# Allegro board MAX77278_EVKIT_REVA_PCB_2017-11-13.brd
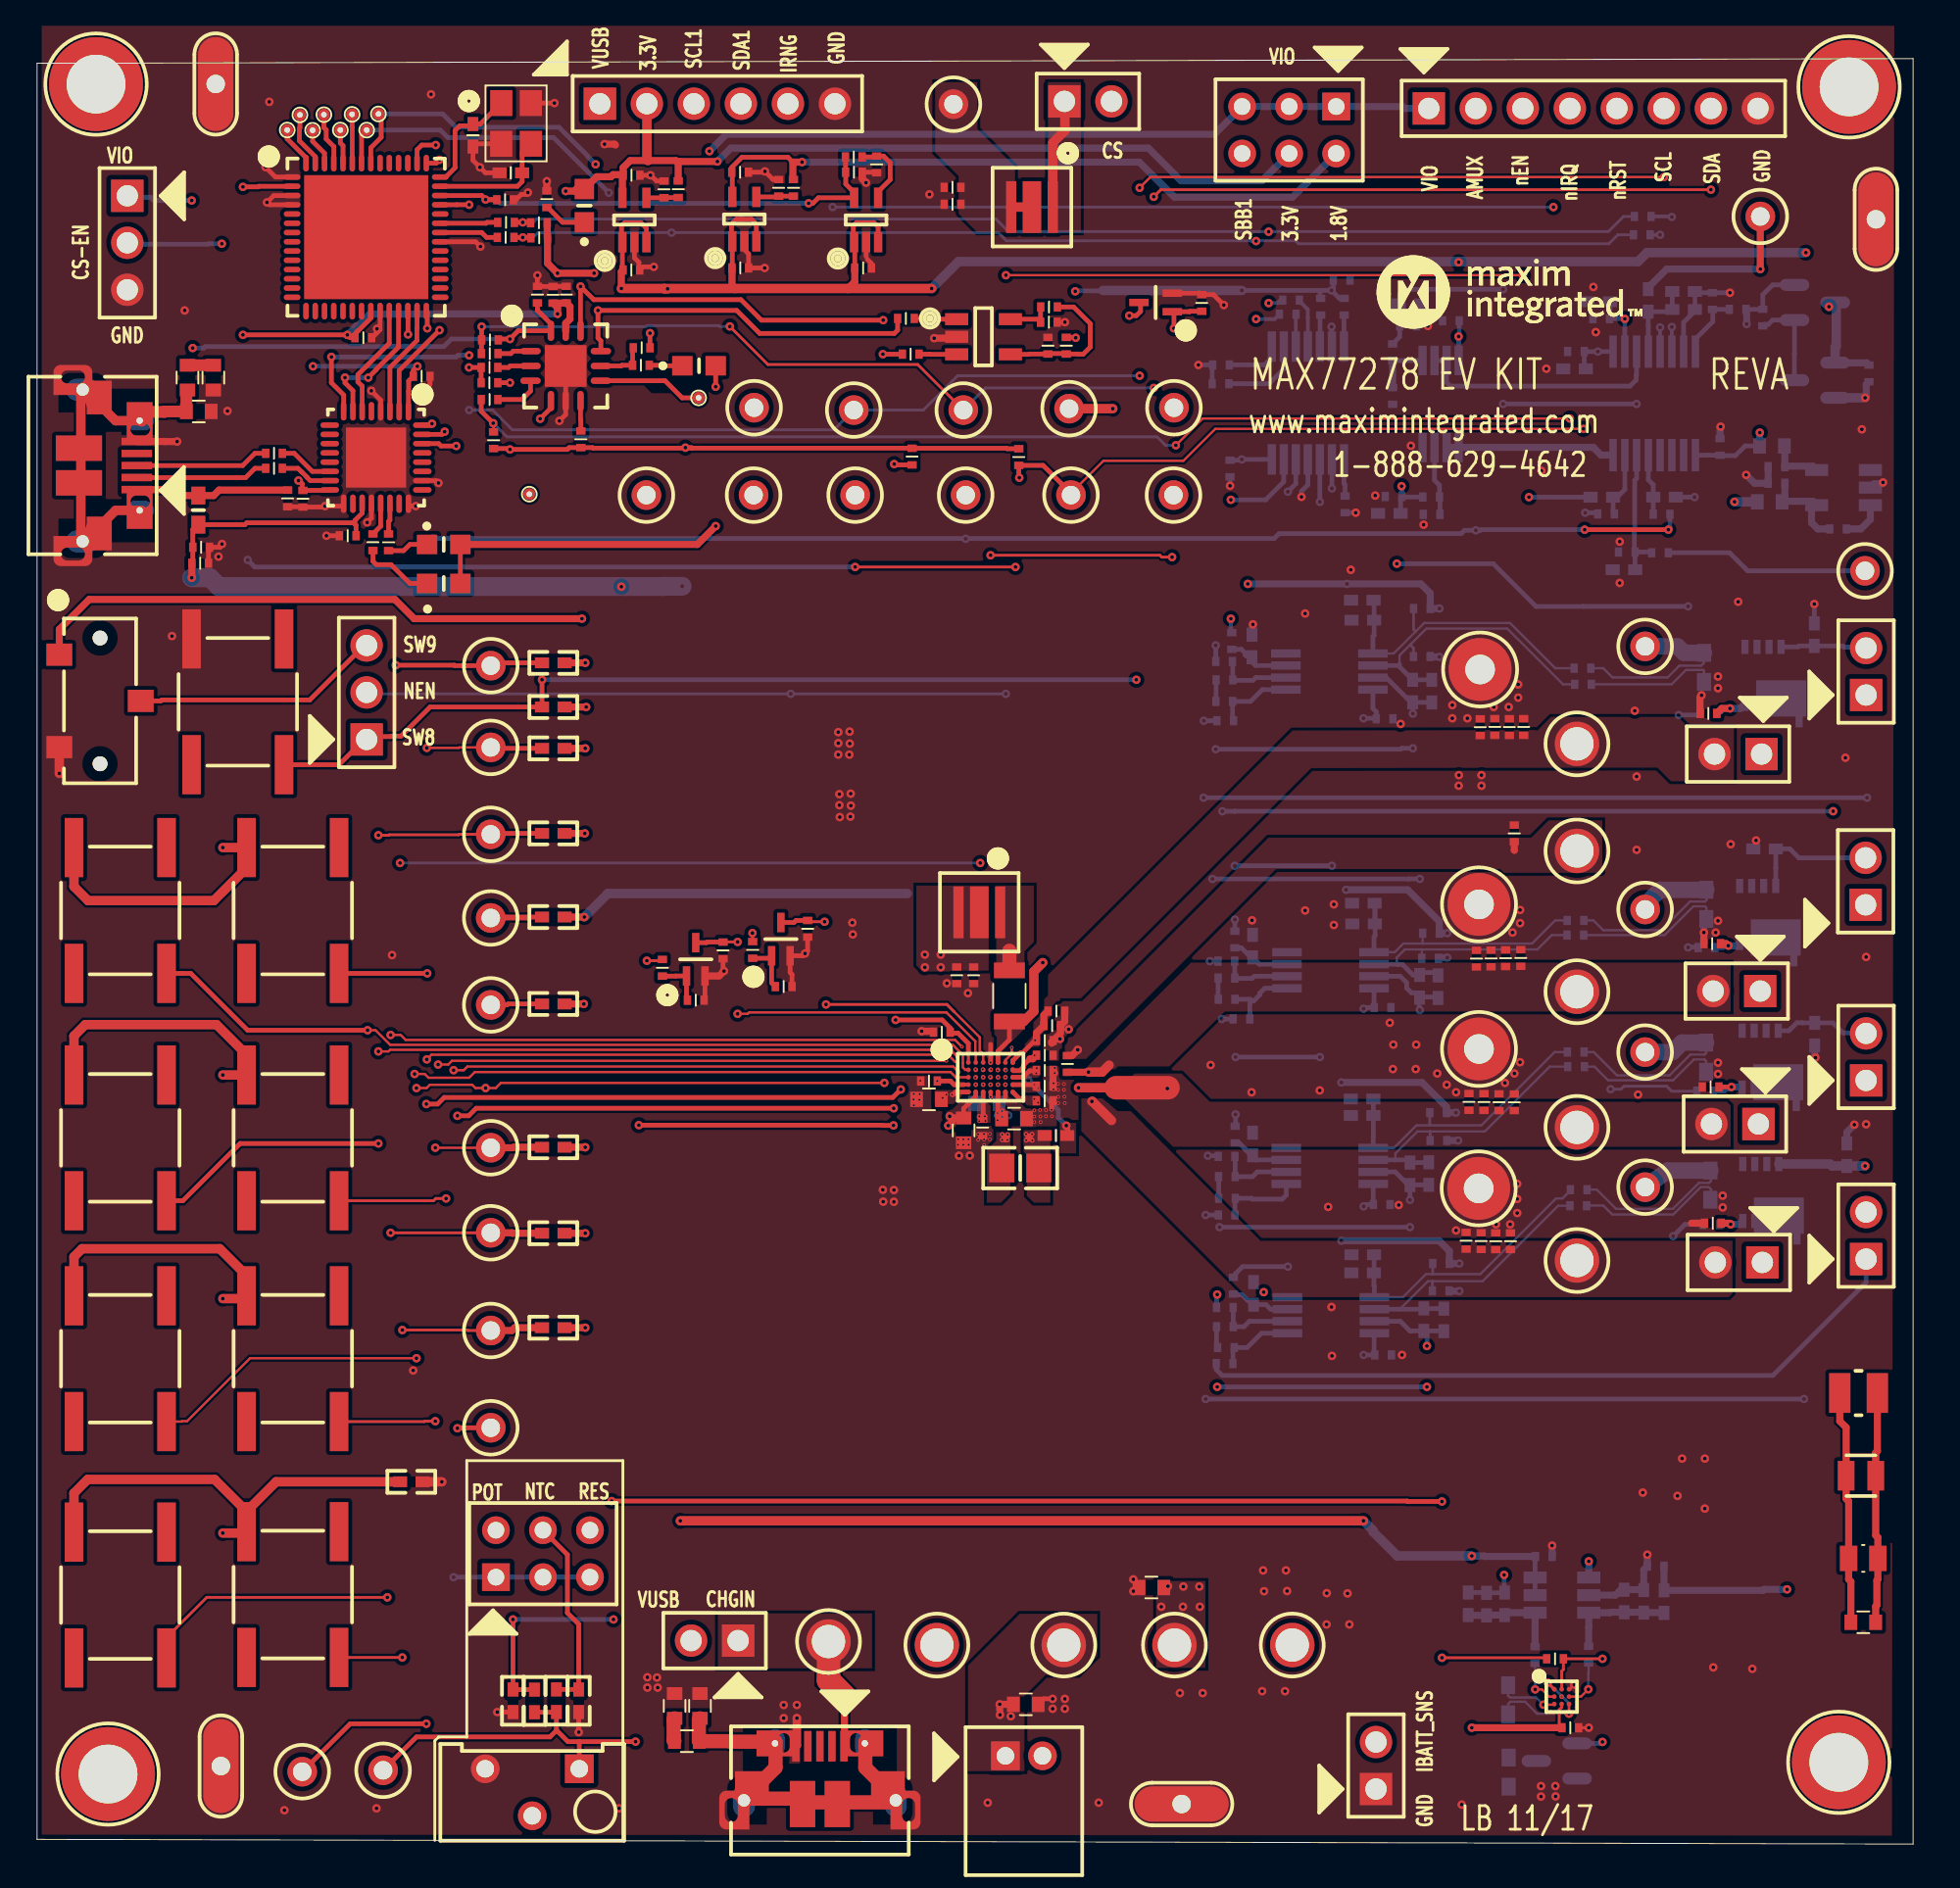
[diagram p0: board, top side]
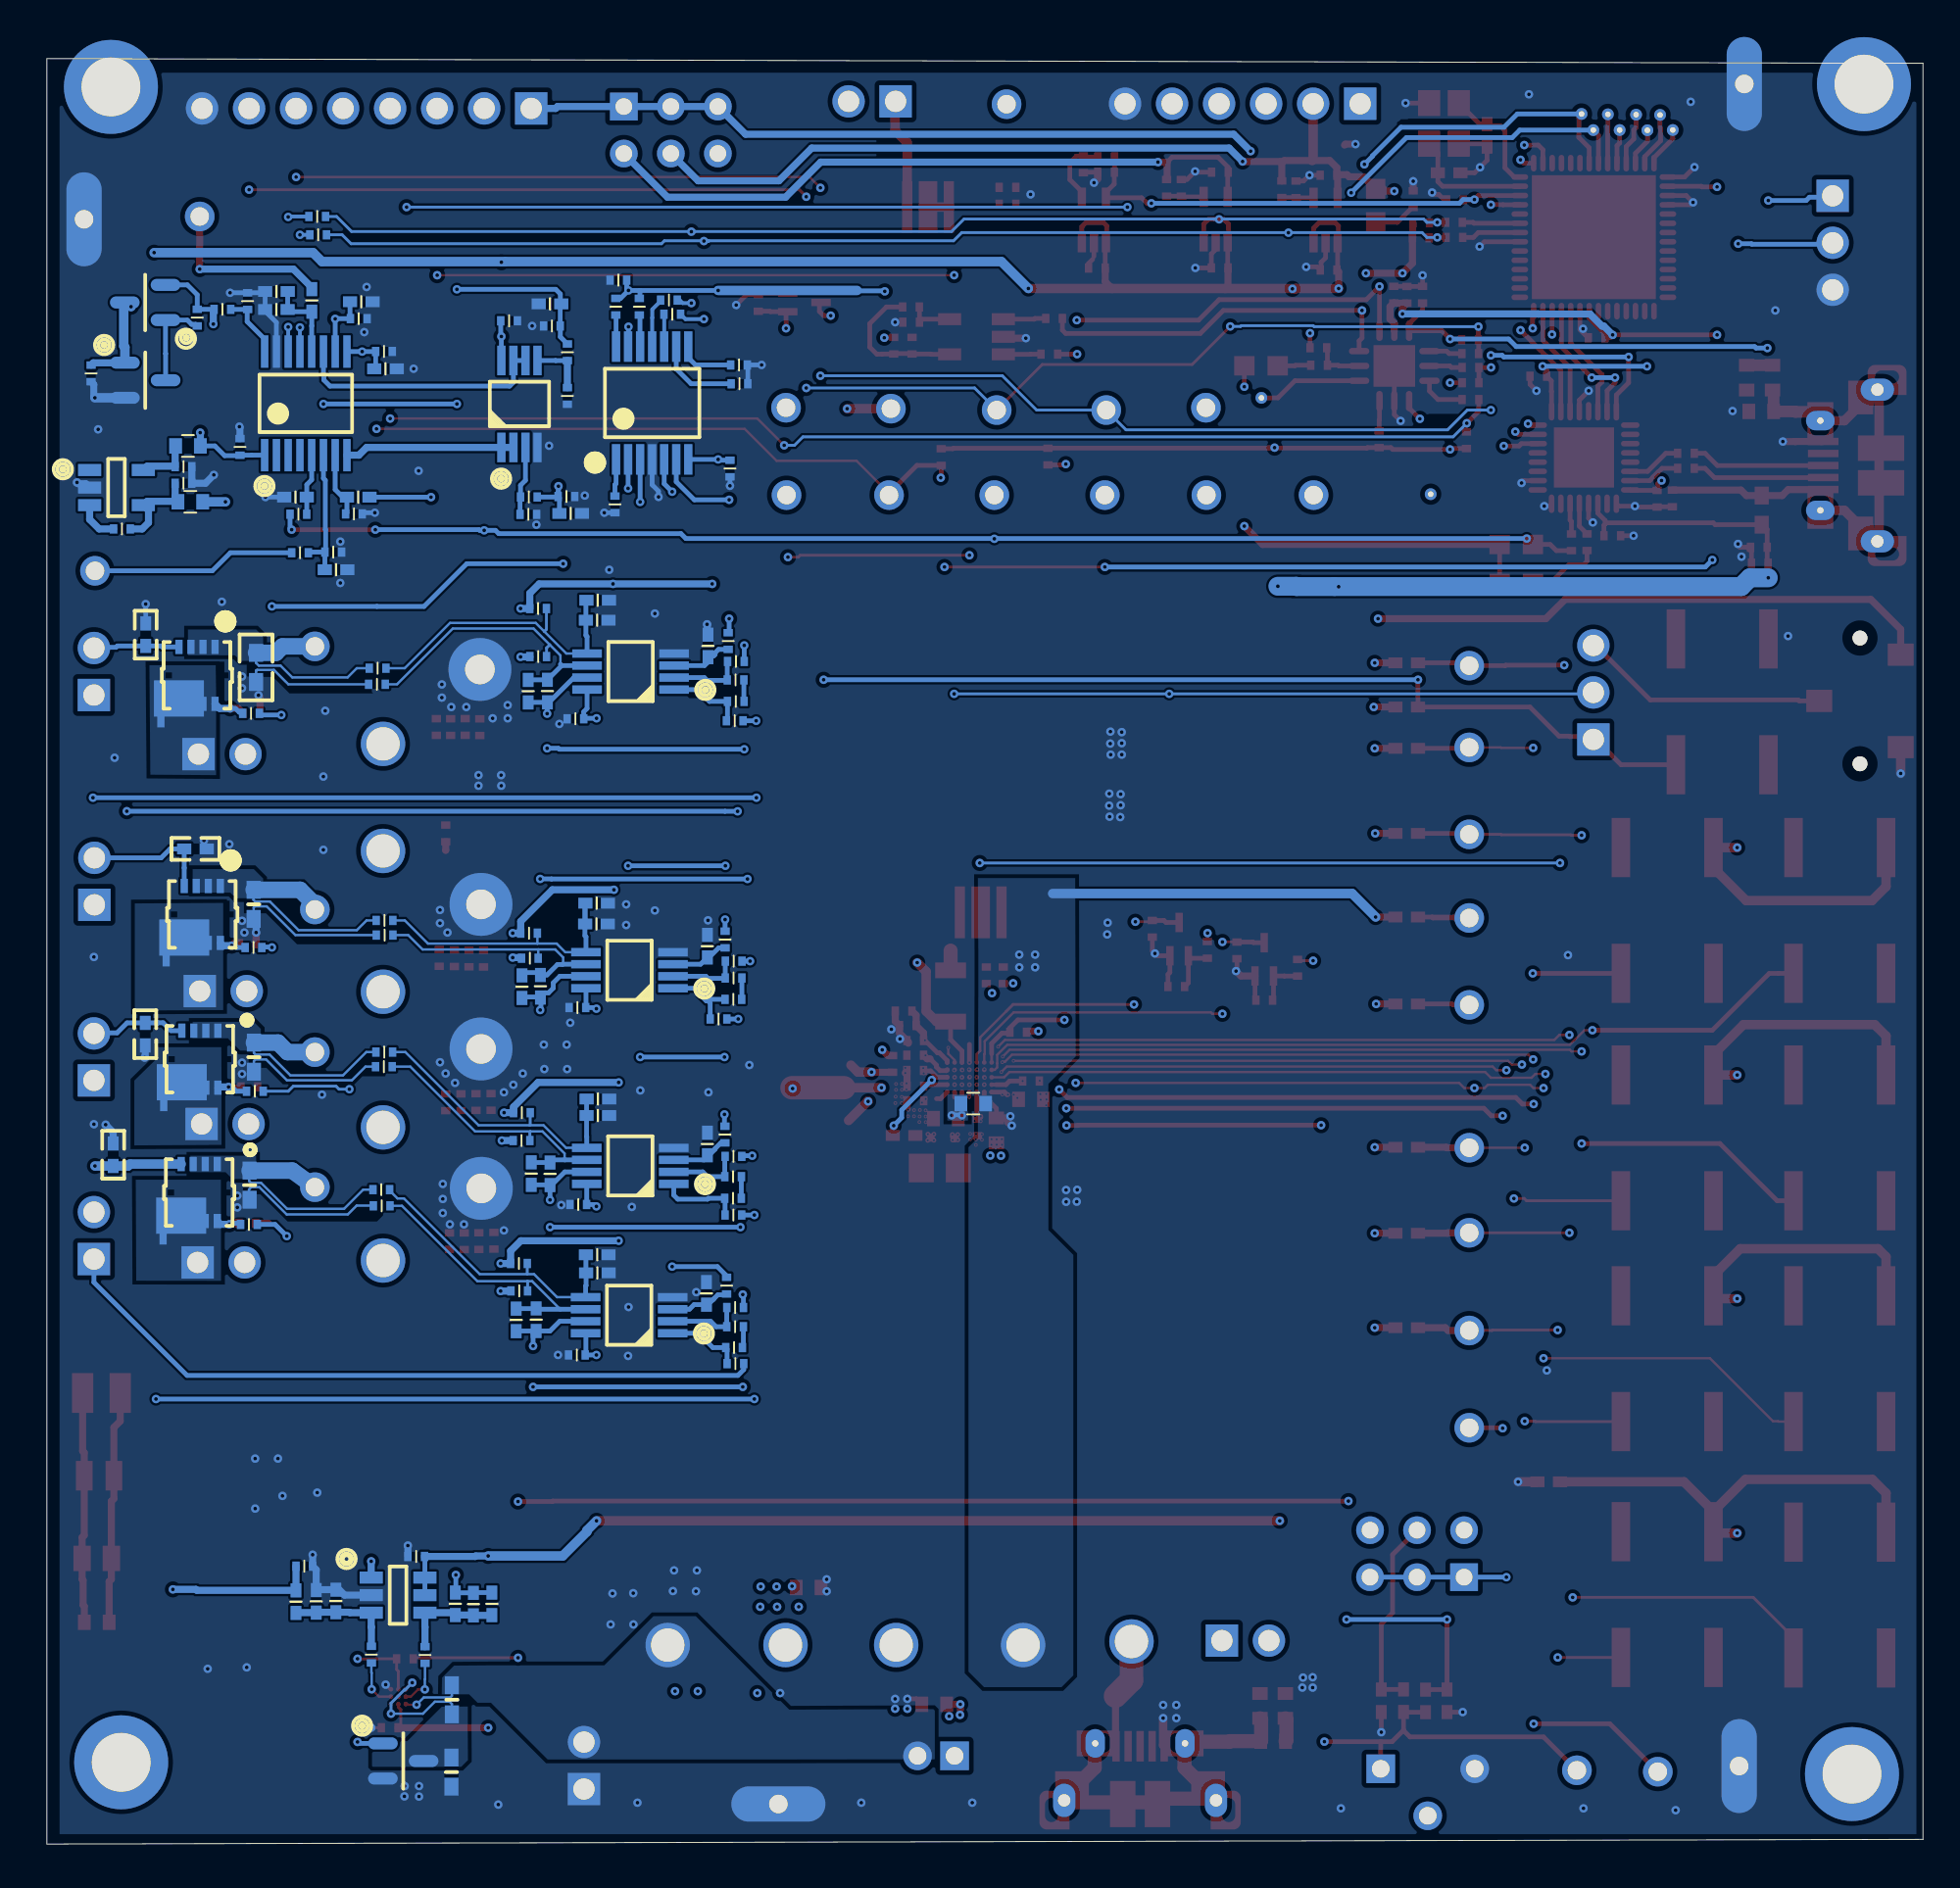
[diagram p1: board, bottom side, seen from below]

Outline 101.35 x 96.52 mm; copper layers: TOP, INTERNAL2, INTERNAL3, BOTTOM. Coordinates in mm from the lower left corner of the outline.
Outline path: 0,96.27 0,0.25 101.35,0 101.35,96.52 0,96.27

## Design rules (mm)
constraint set DEFAULT: min track width 0.102
net group NIRQ: nets NIRQ UNNAMED_4_EKRESSMD_I87_1
net group NIRQ1: nets NIRQ1 UNNAMED_4_EKRESSMD_I190_2
net group UNNAMED_1_10103592-0001LF_I172_SHIELD10: nets UNNAMED_1_10103592-0001LF_I172_SHIELD10 UNNAMED_1_EKCAPNP_I55_1
net group UNNAMED_4_10103592-0001LF_I212_2: nets UNNAMED_4_10103592-0001LF_I212_2 UNNAMED_4_EKRESSMD_I15_2
net group UNNAMED_4_10103592-0001LF_I212_3: nets UNNAMED_4_10103592-0001LF_I212_3 UNNAMED_4_EKRESSMD_I16_2
net group UNNAMED_4_10103592-0001LF_I212_SHIELD10: nets UNNAMED_4_10103592-0001LF_I212_SHIELD10 UNNAMED_4_EKCAPNP_I29_1
net group UNNAMED_4_EKRESSMD_I17_1: nets UNNAMED_4_EKRESSMD_I17_1 UNNAMED_4_EKRESSMD_I17_2
net group UNNAMED_4_EKRESSMD_I18_1: nets UNNAMED_4_EKRESSMD_I18_1 UNNAMED_4_EKRESSMD_I18_2
net group UNNAMED_4_EKRESSMD_I149_1: nets UNNAMED_4_EKRESSMD_I149_1 UNNAMED_4_EKRESSMD_I151_2
net group UNNAMED_4_EKRESSMD_I150_1: nets UNNAMED_4_EKRESSMD_I150_1 UNNAMED_4_EKRESSMD_I152_2
net group SCL: nets SCL SDA UNNAMED_4_EKRESSMD_I153_1 UNNAMED_4_EKRESSMD_I154_1 UNNAMED_4_EKRESSMD_I171_2 VIO
net group SCL1: nets SCL1 UNNAMED_4_24AA02_I200_SCL UNNAMED_4_EKRESSMD_I109_1
net group SDA1: nets SDA1 UNNAMED_4_24AA02_I200_SDA UNNAMED_4_EKRESSMD_I113_1

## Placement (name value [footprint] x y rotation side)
AIN1  N/A  [TP_180P120D460H]  98.75 68.83 0 top
AIN7  N/A  [TP_180P120D460H]  93.09 87.99 0 top
AMUX  N/A  [TP_180P120D460H]  50.16 72.92 0 top
BATTN  N/A  [TP_C240H180]  67.81 10.76 0 top
C1  22UF  [CAPC1608X90L]  52.78 39.22 180 top
C2  4.7UF  [0603]  48.18 40.26 0 top
C3  1UF  [CAPC1005X50L]  48.18 41.25 0 top
C4  3300PF  [0402]  55.04 38.3 180 top
C5  10UF  [CAPC1005X50L]  54.44 43.44 180 top
C6  10UF  [CAPC1005X50L]  54.43 40.18 180 top
C7  4.7UF  [CAPC1005X50L]  51.08 38.74 90 top
C8  10UF  [CAPC1005X50L]  54.43 40.97 180 top
C9  10UF  [CAPC1005X50L]  54.44 41.82 180 top
C10  0.47UF  [CAPC1608X90L]  34.44 7.47 90 top
C11  22UF  [CAPC1608X90L]  50.05 38.58 270 top
C12  1UF  [CAPC1005X50L]  48.88 43.89 0 top
C13  10UF  [CAPC1005X50L]  54.44 42.64 0 top
C14  0.1UF  [CAPC1005X50L]  54.61 81 270 top
C15  22UF  [CAPC1608X90L]  53.41 7.55 0 top
C16  OPEN  [CAPC1608X90L]  60.2 13.87 0 top
C17  10UF  [CAPC1005X50L]  77.96 60.38 270 top
C18  OPEN  [CAPC1005X50L]  79.8 54.64 270 top
C19  OPEN  [CAPC1005X50L]  77.76 47.87 270 top
C20  10UF  [CAPC1005X50L]  77.35 40.12 270 top
C21  OPEN  [CAPC1005X50L]  78.55 47.88 270 top
C22  OPEN  [CAPC1005X50L]  78.16 40.11 270 top
C23  OPEN  [CAPC1005X50L]  78.75 60.39 270 top
C24  OPEN  [CAPC1005X50L]  77.2 32.61 270 top
C25  0.1UF  [CAPC1005X50L]  79.54 60.38 270 top
C26  OPEN  [CAPC1005X50L]  78.01 32.6 270 top
C27  0.1UF  [CAPC1005X50L]  79.33 47.89 270 top
C28  0.1UF  [CAPC1005X50L]  78.98 40.1 270 top
C29  0.1UF  [CAPC1005X50L]  78.8 32.59 270 top
C30  0.01UF  [CAPC1005X50L]  80.15 47.9 270 top
C31  0.01UF  [CAPC1005X50L]  79.8 40.1 270 top
C32  0.01UF  [CAPC1005X50L]  79.6 32.59 270 top
C33  0.01UF  [CAPC1005X50L]  80.31 60.39 270 top
C34  1UF  [CAPC1005X50L]  49.68 46.96 90 top
C35  0.1UF  [0402#2]  50.6 46.96 90 top
C36  10UF  [CAPC1005X50L]  54.84 44.25 180 top
C37  OPEN  [CAPC1005X50L]  55.07 45.03 180 top
C38  1UF  [CAPC1005X50L]  49.45 88.65 0 top
C39  0.1UF  [0402#2]  49.45 89.56 0 top
C108  0.1UF  [CAPC1005X50L]  16.78 70.73 0 top
C110  1UF  [CAPC1005X50L]  37.99 85.2 180 top
C111  1UF  [CAPC1005X50L]  37.98 90.38 180 top
C112  1UF  [CAPC1005X50L]  44.63 85.2 180 top
C113  1UF  [CAPC1005X50L]  44.13 90.38 180 top
C114  0.47UF  [CAPC1608X90L]  9.52 79.27 270 top
C115  1UF  [CAPC1005X50L]  28.59 83.76 270 top
C118  1UF  [CAPC1005X50L]  32.11 85.09 180 top
C120  1UF  [CAPC1005X50L]  27.03 83.76 270 top
C129  OPEN  [CAPC1005X50L]  37.06 48.31 90 top
C134  OPEN  [CAPC1005X50L]  41.63 49.48 90 top
C150  0.1UF  [CAPC1005X50L]  17.63 81.43 0 top
C151  0.1UF  [CAPC1005X50L]  25.29 88.89 0 top
C152  15PF  [0402]  23.55 92.37 90 top
C153  15PF  [0402]  25.6 90.35 0 top
C154  4.7UF  [CAPC1005X50L]  8.86 70.1 180 top
C155  0.1UF  [CAPC1005X50L]  13.54 72.75 270 top
C156  0.1UF  [CAPC1005X50L]  14.36 72.73 90 top
C157  0.1UF  [CAPC1005X50L]  27.88 83.75 270 top
C158  1UF  [CAPC1005X50L]  32.11 90.21 180 top
C159  0.1UF  [CAPC1005X50L]  20.78 79.35 0 top
C200  4700PF  [0402]  65.67 48.54 270 bottom
C201  1000PF  [CAPC1005X50L]  64.25 46.82 180 bottom
C202  0.1UF  [CAPC1005X50L]  72.69 45.22 0 bottom
C203  18PF  [0402]  74.69 46.37 90 bottom
C204  18PF  [0402]  71.66 49.74 0 bottom
C205  4700PF  [0402]  73.05 71.93 0 bottom
C206  1000PF  [CAPC1005X50L]  64.28 36.08 180 bottom
C207  0.1UF  [CAPC1005X50L]  72.64 34.57 0 bottom
C208  18PF  [0402]  71.58 39.38 0 bottom
C209  18PF  [0402]  75.18 36.25 90 bottom
C210  4700PF  [0402]  83.05 79.75 0 bottom
C211  1000PF  [CAPC1005X50L]  64.17 27.97 180 bottom
C212  0.1UF  [CAPC1005X50L]  72.72 26.44 0 bottom
C213  18PF  [0402]  74.92 28.35 90 bottom
C214  18PF  [0402]  71.61 30.88 0 bottom
C215  4700PF  [0402]  84.36 83.38 0 bottom
C216  1000PF  [CAPC1005X50L]  64.14 62.93 180 bottom
C217  0.1UF  [CAPC1005X50L]  72.8 60.83 0 bottom
C218  18PF  [0402]  71.62 66.16 0 bottom
C219  18PF  [0402]  74.31 62.33 90 bottom
C220  4700PF  [0402]  74.17 83.26 180 bottom
C221  0.1UF  [CAPC1005X50L]  70.48 84.55 180 bottom
C222  0.1UF  [CAPC1005X50L]  64.45 74.36 90 bottom
C223  0.1UF  [CAPC1005X50L]  70.66 72.42 90 bottom
C224  0.1UF  [CAPC1005X50L]  82.83 6.29 0 top
C225  330PF  [0402]  79.28 12.99 90 bottom
C226  0.1UF  [CAPC1005X50L]  81.4 15.55 0 bottom
C227  180PF  [0402]  86.8 13.12 90 bottom
C228  1UF  [CAPC1005X50L]  84.76 71.91 0 bottom
C229  0.1UF  [CAPC1005X50L]  76.38 82.35 180 bottom
C234  0.1UF  [CAPC1005X50L]  93.97 73.56 0 bottom
C235  0.1UF  [CAPC1005X50L]  93.97 74.46 0 bottom
C236  0.1UF  [CAPC1005X50L]  87.44 15.02 0 bottom
C237  0.1UF  [CAPC1005X50L]  90.5 83.41 270 bottom
C238  4700PF  [0402]  88.95 83.93 180 bottom
C239  1UF  [CAPC1005X50L]  90.49 48.67 0 top
C240  1UF  [CAPC1005X50L]  90.41 40.93 0 top
C241  1UF  [CAPC1005X50L]  90.52 33.56 0 top
C242  1UF  [CAPC1005X50L]  90.29 61.12 0 top
C244  0.1UF  [CAPC1005X50L]  90.92 75.53 270 bottom
C248  4700PF  [0402]  65.67 37.85 270 bottom
C249  4700PF  [0402]  87.92 72.82 180 bottom
C250  4700PF  [0402]  65.72 29.77 270 bottom
C251  4700PF  [0402]  65.63 64.77 270 bottom
C252  4700PF  [0402]  85.72 68.89 0 bottom
CHGIN  N/A  [TP_C240H180]  42.76 10.95 0 top
CS  N/A  [TP_180P120D460H]  55.75 77.6 0 top
CS_EN  N/A  [TP_180P120D460H]  44.2 72.92 0 top
D100  LTST-C190YKT  [LEDC1608X80M]  21.97 70.26 0 top
D101  LTST-C190YKT  [LEDC1608X80M]  21.97 68.15 0 top
D102  LTST-C190CKT  [LEDC1608X80M]  29.57 88.57 90 top
D103  LTST-C190CKT  [LEDC1608X80M]  35.76 79.92 0 top
DS1  Q65111A2364  [LED_SFH47XX]  50.9 50.37 270 top
DS2  Q65111A2364  [LED_SFH47XX]  53.75 88.49 270 top
EN_EXT  N/A  [TP_180P120D460H]  61.42 77.65 0 top
FB100  220  [0603#2]  8.71 72.11 270 top
GND1  N/A  [TP_C340H160]  77.96 63.5 90 top
GND2  MAXIMPAD  [EVK_MAXIMPAD]  61.83 2.16 180 top
GND3  MAXIMPAD  [EVK_MAXIMPAD]  9.65 95.15 90 top
GND4  MAXIMPAD  [EVK_MAXIMPAD]  99.34 87.83 90 top
GND5  N/A  [TP_C340H160]  77.88 35.45 0 top
GND6  N/A  [TP_C340H160]  77.89 42.98 0 top
GND7  N/A  [TP_C340H160]  77.9 50.8 0 top
GND8  MAXIMPAD  [EVK_MAXIMPAD]  9.93 4.22 90 top
GPIO0  N/A  [TP_180P120D460H]  24.51 63.7 0 top
GPIO1  N/A  [TP_180P120D460H]  24.51 59.28 0 top
GPIO2  N/A  [TP_180P120D460H]  24.51 54.58 0 top
GPIO3  N/A  [TP_180P120D460H]  24.51 50.06 0 top
GPIO4  N/A  [TP_180P120D460H]  24.51 45.36 0 top
GPIO5  N/A  [TP_180P120D460H]  24.51 37.64 0 top
GPIO6  N/A  [TP_180P120D460H]  24.51 33.05 0 top
GPIO7  N/A  [TP_180P120D460H]  24.51 27.76 0 top
I/OVCC4  N/A  [TP_C25H12]  35.74 78.18 0 top
I/OVL4  N/A  [TP_C25H12]  26.59 72.97 0 top
IN_SBB  N/A  [TP_C240H180]  61.45 10.76 0 top
INLDO  N/A  [TP_C240H180]  83.19 53.69 0 top
J1  10103592-0001LF  [FCI_10103592-0001LF]  42.29 2.36 0 top
J2  PBC08SAAN  [SULLINS_PXC08SAAN]  75.18 93.83 0 top
J3  TSW-102-26-T-T  [SAMTEC_TSW-102-26-X-T]  24.79 14.43 90 top
J4  TSW-102-07-T-S  [SAMTEC_TSW-102-07-X-S]  37.87 11 180 top
J5  TSW-102-07-T-S  [SAMTEC_TSW-102-07-X-S]  55.5 94.21 0 top
J6  10103592-0001LF  [FCI_10103592-0001LF]  2.46 74.52 270 top
J7  TSW-103-07-T-S  [SAMTEC_TSW-103-07-T-S]  4.88 89.1 270 top
J8  TSW-103-07-T-S  [SAMTEC_TSW-103-07-T-S]  17.81 59.72 90 top
J9  S2B-PH-K-S(LF)(SN)  [JST_S2B-PH-K-X]  52.31 4.77 180 top
J100  PBC06SAAN  [SULLINS_PXC06SAAN]  30.4 94.08 0 top
J101  TSW-102-26-T-T  [SAMTEC_TSW-102-26-X-T]  70.18 93.93 270 top
J200  TSW-102-07-T-S  [SAMTEC_TSW-102-07-X-S]  98.78 50.77 90 top
J201  TSW-102-07-T-S  [SAMTEC_TSW-102-07-X-S]  93.09 46.11 180 top
J202  TSW-102-07-T-S  [SAMTEC_TSW-102-07-X-S]  98.81 41.28 90 top
J203  TSW-102-07-T-S  [SAMTEC_TSW-102-07-X-S]  92.99 38.93 180 top
J204  TSW-102-07-T-S  [SAMTEC_TSW-102-07-X-S]  98.81 31.62 90 top
J205  TSW-102-07-T-S  [SAMTEC_TSW-102-07-X-S]  93.2 31.44 180 top
J206  TSW-102-07-T-S  [SAMTEC_TSW-102-07-X-S]  98.81 62.12 90 top
J207  TSW-102-07-T-S  [SAMTEC_TSW-102-07-X-S]  93.16 58.92 180 top
J208  TSW-102-07-T-S  [SAMTEC_TSW-102-07-X-S]  72.33 2.97 90 top
L1  1.5UH  [0805]  53.11 36.55 180 top
L2  0.47UH  [0603]  98.65 11.99 180 top
L3  2.2UH  [0805#2]  98.65 15.44 180 top
L4  2.2UH  [IND_2016]  98.53 19.91 180 top
L5  2.2UH  [IND_2520]  98.4 24.38 180 top
LDO  N/A  [TP_C240H180]  83.19 59.48 0 top
LEDREM  N/A  [TP_180P120D460H]  49.5 94.06 0 top
NEN  N/A  [TP_180P120D460H]  38.73 77.65 0 top
NIRQ  N/A  [TP_180P120D460H]  61.39 72.92 0 top
NOREF  -  []  112.93 89.1 0 top
NOREF#2  -  []  74.4 83.82 0 top
NOREF#3  -  [unnamed#2]  3.84 3.78 0 top
NOREF#4  -  [unnamed#2]  97.89 94.99 0 top
NOREF#5  -  [unnamed#2]  97.33 4.42 0 top
NOREF#6  -  []  112.93 -9.96 0 top
NOREF#7  -  []  -19.15 89.1 0 top
NOREF#8  -  []  7.52 -17.58 0 top
NOREF#9  -  [unnamed#2]  3.19 95.14 0 top
NOREF#10  -  []  54.25 150.22 0 top
NRST  N/A  [TP_180P120D460H]  55.85 72.92 0 top
PO0  N/A  [TP_C25H12]  18.44 93.53 90 top
PO1  N/A  [TP_C25H12]  17.81 92.66 90 top
PO2  N/A  [TP_C25H12]  17.02 93.51 90 top
PO3  N/A  [TP_C25H12]  16.39 92.66 90 top
PO4  N/A  [TP_C25H12]  15.5 93.49 90 top
PO5  N/A  [TP_C25H12]  14.89 92.65 90 top
PO6  N/A  [TP_C25H12]  14.2 93.48 90 top
PO7  N/A  [TP_C25H12]  13.52 92.66 90 top
Q1  FDY300NZ  [SOT50P160X90-3M]  60.43 83.34 180 top
Q100  FDY300NZ  [SOT50P160X90-3M]  35.59 47.83 90 top
Q101  FDY300NZ  [SOT50P160X90-3M]  40.18 48.92 90 top
Q200  IRFHM8337TRPBF  [TRAN_IRF_PQFN8_SINGLE_B]  92.95 50.26 270 bottom
Q201  IRFHM8337TRPBF  [TRAN_IRF_PQFN8_SINGLE_B]  93.08 42.43 270 bottom
Q202  IRFHM8337TRPBF  [TRAN_IRF_PQFN8_SINGLE_B]  93.12 35.22 270 bottom
Q203  IRFHM8337TRPBF  [TRAN_IRF_PQFN8_SINGLE_B]  93.24 63.18 270 bottom
Q204  DMG3420U  [SOT95P237X112-3M]  82.09 4.49 180 bottom
Q205  FDN360P  [SOT95P237X112-3M]  96.04 83.34 0 bottom
Q206  2N7002  [SOT95P237X112-3M]  96.03 79.13 180 bottom
QSCL  N/A  [TP_180P120D460H]  38.71 72.92 0 top
QSDA  N/A  [TP_180P120D460H]  32.92 72.92 0 top
R1  10K  [0402]  28.06 7.75 90 top
R2  10K  [0402]  27.89 61.47 180 top
R3  0  [RESC1608X90L]  35.1 5.56 180 top
R4  1M  [RESC1608X90L]  35.81 7.47 90 top
R5  0  [RESC1608X90L]  51.3 40.03 0 bottom
R6  100K  [0402]  27.89 50.11 180 top
R7  100K  [0402#2]  62.92 83.31 90 top
R8  100K  [0402]  27.89 45.42 0 top
R9  0  [1206]  52.53 45.85 270 top
R10  470K  [0402#2]  53.04 74.98 90 top
R11  0  [RESC1005X50L]  55.66 42.17 270 top
R12  200K  [BOURNS_3296Y]  26.75 2.8 0 top
R13  10K  [0402]  25.71 7.74 270 top
R14  470K  [0402#2]  24.66 75.89 270 top
R15  10K  [0402]  26.87 7.74 90 top
R16  100K  [0402]  27.89 54.64 180 top
R17  0  [RESC1005X50L]  47.27 75.01 90 top
R18  100K  [0402]  27.89 37.67 0 top
R19  100K  [0402]  27.89 59.23 180 top
R20  100K  [0402]  27.89 33.02 0 top
R21  100K  [0402]  27.89 63.86 180 top
R22  100K  [0402]  27.89 27.91 0 top
R23  100  [0402]  20.22 19.58 0 top
R100  4.7K  [RESC1005X50L]  27.11 87.65 0 top
R103  22  [RESC1005X50L]  12.8 75.18 0 top
R107  2.2K  [RESC1005X50L]  24.44 79 180 top
R108  2.2K  [RESC1005X50L]  24.47 81.32 180 top
R109  100  [RESC1005X50L]  18.15 70.38 270 top
R110  470  [0402#2]  27.54 88.92 90 top
R111  100  [RESC1005X50L]  18.99 70.37 270 top
R115  100K  [RESC1005X50L]  8.81 69.24 0 top
R118  4.7K  [RESC1005X50L]  27.13 86.83 0 top
R122  1M  [RESC1608X90L]  8.74 77.44 0 top
R123  22  [RESC1005X50L]  12.8 74.37 0 top
R135  0  [RESC1005X50L]  24.46 80.57 180 top
R136  0  [RESC1005X50L]  24.44 79.82 180 top
R137  49.9  [RESC1005X50L]  40.34 46.35 0 top
R138  49.9  [RESC1005X50L]  35.59 45.62 0 top
R139  0  [RESC1005X50L]  38.66 48.34 90 top
R141  0  [RESC1005X50L]  33.78 47.37 90 top
R142  0  [RESC1608X90L]  8.13 79.27 90 top
R143  0  [RESC1005X50L]  29.38 75.94 90 top
R148  0  [RESC1005X50L]  25.34 87.67 0 top
R150  22  [RESC1005X50L]  24.45 78.09 180 top
R151  150  [0402#2]  32.62 79.94 180 top
R152  0  [RESC1005X50L]  32.66 80.89 180 top
R155  0  [RESC1005X50L]  25.32 86.85 0 top
R156  105K  [0402#2]  44.12 91.2 0 top
R157  100K  [RESC1005X50L]  45.35 90.8 270 top
R158  169K  [0402#2]  34.64 89.46 270 top
R159  100K  [RESC1005X50L]  33.87 89.45 90 top
R160  47.5K  [0402#2]  40.86 89.53 270 top
R161  100K  [RESC1005X50L]  40.06 89.53 90 top
R162  0  [RESC1005X50L]  46.94 82.47 0 top
R163  0  [RESC1005X50L]  55.6 81 90 top
R164  0  [RESC1005X50L]  47.19 80.54 180 top
R165  OPEN  [RESC1005X50L]  54.67 83.09 180 top
R166  0  [RESC1005X50L]  54.66 82.27 0 top
R201  100  [0402#2]  64.26 45.67 0 bottom
R202  680  [0402#2]  64.24 47.73 180 bottom
R203  20K  [0402#2]  64.71 48.9 270 bottom
R204  0  [RESC1005X50L]  65.06 44.6 180 bottom
R205  4.99K  [0402]  75.68 46.35 90 bottom
R206  4.99K  [0402]  71.65 50.86 0 bottom
R207  1K  [RESC1005X50L]  83.11 49.93 0 bottom
R208  1K  [RESC1005X50L]  83.1 49.14 0 bottom
R210  1M  [0402]  93.32 53.8 0 bottom
R211  1  [0603#2]  90.18 50.8 270 bottom
R212  0  [RESC1005X50L]  90.18 48.47 180 bottom
R213  OPEN  [RESC1005X50L]  73.28 72.85 180 bottom
R214  100K  [RESC1005X50L]  70.61 83.11 90 bottom
R222  100  [0402#2]  64.28 34.91 0 bottom
R223  680  [0402#2]  64.26 37.17 180 bottom
R224  20K  [0402#2]  64.72 38.36 270 bottom
R225  0  [RESC1005X50L]  64.26 34.01 180 bottom
R226  4.99K  [0402]  71.58 40.28 0 bottom
R227  0  [RESC1005X50L]  90.11 40.7 180 bottom
R228  4.99K  [0402]  74.17 36.23 90 bottom
R229  1K  [RESC1005X50L]  83.12 42.82 0 bottom
R230  1K  [RESC1005X50L]  83.14 42.03 0 bottom
R231  1M  [0402]  96.03 43.78 90 bottom
R233  1  [0603#2]  90.16 42.54 270 bottom
R234  OPEN  [RESC1005X50L]  83.13 80.69 180 bottom
R235  100  [0402#2]  64.22 26.84 0 bottom
R236  680  [0402#2]  64.17 29 180 bottom
R237  20K  [0402#2]  64.63 30.19 270 bottom
R238  0  [RESC1005X50L]  64.15 25.97 180 bottom
R239  4.99K  [0402]  76 28.33 90 bottom
R240  4.99K  [0402]  71.62 31.86 0 bottom
R242  1K  [RESC1005X50L]  83.28 35.38 0 bottom
R243  1K  [RESC1005X50L]  83.26 34.5 0 bottom
R244  1M  [0402]  97.76 37.27 270 bottom
R245  1  [0603#2]  90.39 35.62 270 bottom
R246  0  [RESC1005X50L]  90.43 33.5 180 bottom
R247  OPEN  [RESC1005X50L]  84.5 82.46 180 bottom
R248  100  [0402#2]  64.13 61.77 0 bottom
R249  680  [0402#2]  64.12 63.93 180 bottom
R250  20K  [0402#2]  64.54 65.03 270 bottom
R251  0  [RESC1005X50L]  64.19 60.72 180 bottom
R252  4.99K  [0402]  71.59 67.24 0 bottom
R253  4.99K  [0402]  75.35 62.32 90 bottom
R254  1K  [RESC1005X50L]  83.48 63.57 0 bottom
R255  1K  [RESC1005X50L]  83.52 62.7 0 bottom
R257  1M  [0402]  96.01 65.38 270 bottom
R258  1  [0603#2]  90.05 63.61 270 bottom
R259  0  [RESC1005X50L]  90.32 61.13 180 bottom
R260  OPEN  [RESC1005X50L]  74.07 82.07 0 bottom
R261  0.1  [0603#2]  79.47 7.8 270 bottom
R262  10  [0603#2]  79.49 3.89 270 bottom
R263  1K  [RESC1005X50L]  80.92 10.22 90 bottom
R264  1K  [RESC1005X50L]  83.82 10.24 90 bottom
R265  64.9K  [0402]  87.89 13.1 270 bottom
R266  64.9K  [0402]  78.3 12.97 90 bottom
R267  64.9K  [0402]  77.31 12.99 90 bottom
R268  64.9K  [0402]  85.74 13.14 90 bottom
R269  1K  [0402]  84.53 72.81 0 bottom
R271  10M  [0402#2]  75.31 72.82 0 bottom
R272  10M  [0402#2]  75.34 71.88 180 bottom
R273  10M  [0402#2]  73.23 80.64 270 bottom
R274  10M  [0402#2]  73.23 78.28 270 bottom
R277  0  [RESC1608X90L]  93.6 72.56 0 bottom
R279  0  [RESC1608X90L]  93.72 75.58 180 bottom
R280  100K  [RESC1005X50L]  97.29 71.09 0 bottom
R281  10K  [0402]  87.04 83.45 270 bottom
R282  10K  [0402]  88.95 82.96 0 bottom
R283  100K  [RESC1005X50L]  69.34 83.11 270 bottom
R284  100K  [0402#2]  82 10.02 0 top
R285  0  [RESC1005X50L]  87.76 71.89 180 bottom
R286  0  [RESC1005X50L]  91.87 82.96 180 bottom
R287  10K  [0402#2]  98.96 79.5 270 bottom
R288  10K  [0402#2]  93.22 82.52 270 bottom
R293  470K  [0402#2]  75.3 49.24 0 bottom
R294  649K  [0402#2]  75.26 47.89 180 bottom
R295  470K  [0402#2]  75.69 39.54 0 bottom
R296  649K  [0402#2]  75.71 38.03 180 bottom
R297  470K  [0402#2]  75.85 31.39 0 bottom
R298  649K  [0402#2]  75.83 29.9 180 bottom
R299  470K  [0402#2]  74.81 66.79 0 bottom
R300  649K  [0402#2]  74.81 64.19 180 bottom
R301  1M  [0402#2]  85.88 69.84 180 bottom
R302  0  [RESC1005X50L]  87.67 69.81 180 bottom
R303  0  [RESC1005X50L]  86.74 87.99 0 bottom
R304  0  [RESC1005X50L]  86.69 87 0 bottom
R305  0  [RESC1005X50L]  67.56 82.7 0 bottom
R306  0  [RESC1005X50L]  67.74 83.46 0 bottom
R307  0  [RESC1005X50L]  63.93 78.94 0 bottom
R308  0  [RESC1005X50L]  63.96 79.96 0 bottom
RT1  10K  [0402]  29.26 7.74 270 top
SBB0  N/A  [TP_C240H180]  83.19 46.08 0 top
SBB1  N/A  [TP_C240H180]  83.19 38.74 0 top
SBB2  N/A  [TP_C240H180]  83.19 31.55 0 top
SCL  N/A  [TP_180P120D460H]  44.12 77.52 0 top
SDA  N/A  [TP_180P120D460H]  50.04 77.52 0 top
SW0  EVQ-Q2K03W  [SW_EVQ-Q2X03W]  4.5 50.47 270 top
SW1  EVQ-Q2K03W  [SW_EVQ-Q2X03W]  13.82 50.47 270 top
SW2  EVQ-Q2K03W  [SW_EVQ-Q2X03W]  4.5 38.18 270 top
SW3  EVQ-Q2K03W  [SW_EVQ-Q2X03W]  13.82 38.18 270 top
SW4  EVQ-Q2K03W  [SW_EVQ-Q2X03W]  4.5 26.24 270 top
SW5  EVQ-Q2K03W  [SW_EVQ-Q2X03W]  13.82 26.24 270 top
SW6  EVQ-Q2K03W  [SW_EVQ-Q2X03W]  4.5 13.46 270 top
SW7  EVQ-Q2K03W  [SW_EVQ-Q2X03W]  13.82 13.49 270 top
SW8  EVQ-Q2K03W  [SW_EVQ-Q2X03W]  10.85 61.75 90 top
SW9  CL-SB-12B-11  [SW_CL-SB-12B-1X]  3.4 61.8 0 top
TBIAS  N/A  [TP_180P120D460H]  18.69 3.99 0 top
THM  N/A  [TP_180P120D460H]  24.51 22.5 0 top
U1  MAX77278  [BGA35C40P7X5_314X214X69M]  51.51 41.45 0 top
U100  MAXQ2000-RBX+  [QFN50P800X800X80-57M]  17.78 86.87 0 top
U101  FT232RQ  [QFN50P500X500X100-33V2M]  18.31 74.96 270 top
U102  MAX8512EXK  [SOT65P210X110-5M]  32.27 87.79 90 top
U103  MAX8512EXK  [SOT65P210X110-5M]  38.21 87.84 90 top
U104  MAX8512EXK  [SOT65P210X110-5M]  44.79 87.8 90 top
U107  MAX3395EETC  [QFN80P400X400X80-13M]  28.56 79.91 0 top
U108  24AA02T-I/OT  [SOT95P280X145-5M]  51.13 81.48 0 top
U200  MAX44251AUA+  [SOP65P490X110-8M]  69.87 47.24 0 bottom
U201  MAX44251AUA+  [SOP65P490X110-8M]  69.83 36.66 0 bottom
U202  MAX44251AUA+  [SOP65P490X110-8M]  69.89 28.59 0 bottom
U203  MAX44251AUA+  [SOP65P490X110-8M]  69.82 63.38 0 bottom
U204  MAX44251AUA+  [SOP65P490X110-8M]  75.82 77.85 90 bottom
U205  MAX5815AAUD+  [SOP65P640X120-14M]  68.65 77.9 90 bottom
U206  MAX14689EWL+  [BGA9C40P3X3_126X126X69M]  82.36 7.97 0 top
U207  MAX4238AUT+  [SOT95P280X145-6M]  82.38 13.46 180 bottom
U209  MAX11614EEE+  [SOP63P600X175-16M]  87.36 77.88 90 bottom
U210  MAX6037BAUK41+  [SOT95P280X145-5M]  97.59 73.33 180 bottom
VBATT  N/A  [TP_C240H180]  55.47 10.76 0 top
VIL_LDO  N/A  [TP_180P120D460H]  86.87 64.74 0 top
VIL_SBB0  N/A  [TP_180P120D460H]  86.87 50.52 0 top
VIL_SBB1  N/A  [TP_180P120D460H]  86.87 42.81 0 top
VIL_SBB2  N/A  [TP_180P120D460H]  86.87 35.51 0 top
VL  N/A  [TP_180P120D460H]  14.33 3.91 0 top
VSYS  N/A  [TP_C240H180]  48.61 10.76 0 top
Y101  16MHZ  [XTAL320X250X070M]  25.88 93.02 270 top

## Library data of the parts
AIN1 AIN7 LEDREM TBIAS THM VIL_LDO VIL_SBB0-VIL_SBB2 VL = TP: part number: TP_TP-TP_180P120D460H,N/A,02-TPMINI5000-00
AMUX CS CS_EN EN_EXT GPIO0-GPIO7 NEN NIRQ NRST QSCL QSDA SCL SDA = TP: part number: TP_TP-TP_180P120D460H,N/A,02-TPMINI5002-00
BATTN CHGIN IN_SBB INLDO LDO SBB0-SBB2 VBATT VSYS = TP: alternate symbols: TP_C340H160L; part number: TP_TP-TP_C240H180,N/A,02-TPMINI5010-00
C1 C11 C15 = EK_CAP_NP: part number: EK_CAP_NP_0603_FF-CAPC1608X90L,22UF,20-0022U-A48
C2 = CAP_NP: alternate symbols: 0603_NOSILK,CAPC1608X90L; part number: CAP_NP_0603CAP-0603,4.7UF,20-004U7-L3
C3 C12 C34 C38 C110-C113 C115 C118 C120 C158 C239-C242 = EK_CAP_NP: part number: EK_CAP_NP_0402_FF-CAPC1005X50L,1UF,20-0001U-B65
C4 = CAP_NP: alternate symbols: (0402_NOSILK); part number: CAP_NP_0402CAP-0402,3300PF,20-3300P-A0Z
C5 C6 C8 C9 C13 C17 C20 C36 = EK_CAP_NP: part number: EK_CAP_NP_0402_FF-CAPC1005X50L,10UF,20-0010U-B65
C7 = EK_CAP_NP: part number: EK_CAP_NP_0402_FF-CAPC1005X50L,4.7UF,20-004U7-33A
C10 C114 = EK_CAP_NP: part number: EK_CAP_NP_0603_FF-CAPC1608X90L,0.47UF,20-00U47-16; signal model: DEFAULT_CAPACITOR_470000pF_2_1
C14 C156 C157 = EK_CAP_NP: part number: EK_CAP_NP_0402_FF-CAPC1005X50L,0.1UF,20-000U1-12; signal model: DEFAULT_CAPACITOR_100000pF_2_1
C16 = EK_CAP_NP: alternate symbols: 0603,0603_NOSILK; part number: EK_CAP_NP_0603_FF-CAPC1608X90L,OPEN,N/A
C18 C19 C21-C24 C26 C37 = EK_CAP_NP: alternate symbols: 0402,0402_NOSILK; part number: EK_CAP_NP_0402_FF-CAPC1005X50L,OPEN,N/A
C25 C27-C29 = EK_CAP_NP: part number: EK_CAP_NP_0402_FF-CAPC1005X50L,0.1UF,20-000U1-33
C30-C33 = EK_CAP_NP: part number: EK_CAP_NP_0402_FF-CAPC1005X50L,0.01UF,20-00U01-B8
C35 C39 = CAP_NP: alternate symbols: 0402_NOSILK,CAPC1005X50L; part number: CAP_NP_0402CAP-0402,0.1UF,20-000U1-19
C108 C150 C151 C155 C159 C202 C207 C212 C217 C221-C224 C226 C229 C234-C237 C244 = EK_CAP_NP: part number: EK_CAP_NP_0402_FF-CAPC1005X50L,0.1UF,20-000U1-12
C129 C134 = EK_CAP_NP: alternate symbols: 0402,0402_NOSILK; part number: EK_CAP_NP_0402_FF-CAPC1005X50L,OPEN,N/A; signal model: DEFAULT_CAPACITOR_0.001pF_2_1
C152 C153 = CAP_NP: alternate symbols: 0402_NOSILK,CAPC1005X50L; part number: CAP_NP_0402CAP-0402,15PF,20-0015P-F3
C154 = EK_CAP_NP: part number: EK_CAP_NP_0402_FF-CAPC1005X50L,4.7UF,20-004U7-33A; signal model: DEFAULT_CAPACITOR_4.7e+06pF_2_1
C200 C205 C210 C215 C220 C238 C248-C252 = CAP_NP: alternate symbols: (0402_NOSILK); part number: CAP_NP_0402CAP-0402,4700PF,20-4700P-A0Z
C201 C206 C211 C216 = EK_CAP_NP: part number: EK_CAP_NP_0402_FF-CAPC1005X50L,1000PF,20-1000P-E7
C203 C204 C208 C209 C213 C214 C218 C219 = CAP_NP: alternate symbols: 0402_NOSILK,CAPC1005X50L; part number: CAP_NP_0402CAP-0402,18PF,20-0018P-27
C225 = CAP_NP: alternate symbols: (0402_NOSILK); part number: CAP_NP_0402CAP-0402,330PF,20-0330P-27J
C227 = CAP_NP: alternate symbols: (0402_NOSILK); part number: CAP_NP_0402CAP-0402,180PF,20-0180P-27J
C228 = EK_CAP_NP: part number: EK_CAP_NP_0402_FF-CAPC1005X50L,1UF,20-0001U-33
D100 D101 = LED: part number: LED_LEDC1608X80M-LEDC1608X80M,LTST-C190YKT,30-LTSTC190YKT-00
D102 D103 = LED: part number: LED_LEDC1608X80M-LEDC1608X80M,LTST-C190CKT,30-LTSTC190CKT-00
DS1 DS2 = LED_3P: part number: LED_3P_SFH47-LED_SFH47XX,Q65111A2364,30-Q65111A2364-00
FB100 = INDUCT: alternate symbols: (0603_NOSILK); part number: INDUCT_0603-0603,220,50-00220-SM12A; signal model: DEFAULT_INDUCTOR_220.000000nH_1_2
GND1 GND5-GND7 = TP: alternate symbols: TP_C340H160L; part number: TP_TP-TP_C340H160,N/A,02-TPMINI5011-00
GND2-GND4 GND8 = EVK_MAXIMPAD: alternate symbols: EVK_MAXIMPAD_ALT; part number: EVK_MAXIMPAD_MISC-EVK_MAXIMPAD,MAXIMPAD,01-9020BUSS20AWG-00
I/OVCC4 I/OVL4 PO0-PO7 = TP: part number: TP_TP-TP_C25H12,N/A,N/A
J1 J6 = 10103592-0001LF: part number: 10103592-0001LF_SMT-FCI_10103592-0001LF,10103592-0001LF,01-101035920001LF5P-26
J2 = HEADER_8P: part number: HEADER_8P_TH-SULLINS_PXC08SAAN,PBC08SAAN,01-PBC08SAAN8P-21
J3 J101 = HEADER_2P_X_3R: part number: HEADER_2P_X_3R_TH-SAMTEC_TSW-102-26-X-T,TSW-102-26-T-T,01-TSW10226TT6P-17
J4 J5 J200-J208 = HEADER_2P: part number: HEADER_2P_TH-SAMTEC_TSW-102-07-X-S,TSW-102-07-T-S,01-TSW10207TS2P-17
J7 J8 = HEADER_3P: part number: HEADER_3P_SIP-SAMTEC_TSW-103-07-T-S,TSW-103-07-T-S,01-TSW10307TS3P-17
J9 = HEADER_2P: part number: HEADER_2P_RA-JST_S2B-PH-K-X,S2B-PH-K-S(LF)(SN),01-S2BPHKS2P-19
J100 = HEADER_6P: part number: HEADER_6P_TH-SULLINS_PXC06SAAN,PBC06SAAN,01-PBC06SAAN6P-21
L1 = EVKIT_INDUCT: alternate symbols: INDC2012X145L; part number: EVKIT_INDUCT_IND_0805-0805,1.5UH,50-001U5-0LP
L2 = INDUCT: alternate symbols: 0603_NOSILK,INDC1608X90L; part number: INDUCT_0603-0603,0.47UH,50-00U47-0DK
L3 = EVKIT_INDUCT: alternate symbols: INDC2012X145L; part number: EVKIT_INDUCT_IND_0805-0805,2.2UH,50-002U2-0LM
L4 = EVKIT_INDUCT: alternate symbols: INDC2016X100L; part number: EVKIT_INDUCT_IND_0806-IND_2016,2.2UH,50-002U2-0LO
L5 = EVKIT_INDUCT: alternate symbols: INDC2520X120L; part number: EVKIT_INDUCT_2520-IND_2520,2.2UH,50-002U2-0LN
Q1 Q100 Q101 = TRAN_NCH_3P: part number: TRAN_NCH_3P_SC89_TRENCH-SOT50P160X90-3M,FDY300NZ,90-FDY300NZ-28
Q200-Q203 = TRAN_NCH_8P: part number: TRAN_NCH_8P_PQFN8-TRAN_IRF_PQFN8_SINGLE_B,IRFHM8337TRPBF,90-IRFHM8337-10
Q204 = TRAN_NCH_3P: part number: TRAN_NCH_3P_SOT23-SOT95P237X112-3M,DMG3420U,90-DMG3420U-16
Q205 = TRAN_PCH_3P: part number: TRAN_PCH_3P_SOT-23-SOT95P237X112-3M,FDN360P,90-FDC360P-25
Q206 = TRAN_NCH_3P: part number: TRAN_NCH_3P_SOT23-SOT95P237X112-3M,2N7002,90-2N7002-06
R1 R2 R13 R15 R281 R282 R287 R288 = RES: alternate symbols: 0402_NOSILK,RESC1005X50L,RES0402-NOT_FOR_TEST; part number: RES_0402RES-0402,10K,80-0010K-23
R3 R142 = EK_RES_SMD: part number: EK_RES_SMD_0603_FF-RESC1608X90L,0,80-0000R-27; signal model: DEFAULT_RESISTOR_0.001OHM_2_1
R4 R122 = EK_RES_SMD: part number: EK_RES_SMD_0603_FF-RESC1608X90L,1M,80-0001M-19; signal model: DEFAULT_RESISTOR_0.001OHM_2_1
R5 R277 R279 = EK_RES_SMD: part number: EK_RES_SMD_0603_FF-RESC1608X90L,0,80-0000R-27
R6-R8 R16 R18-R22 R284 = RES: alternate symbols: 0402_NOSILK,RESC1005X50L; part number: RES_0402RES-0402,100K,80-0100K-23
R9 = RES: alternate symbols: RESC3116X60L; part number: RES_1206RES-1206,0,80-0000R-29
R10 R14 R293 R295 R297 R299 = RES: alternate symbols: (0402_NOSILK,RESC1005X50L); part number: RES_0402RES-0402,470K,80-0470K-23
R11 R17 R204 R212 R225 R227 R238 R246 R251 R259 R285 R286 R302-R308 = EK_RES_SMD: part number: EK_RES_SMD_0402_FF-RESC1005X50L,0,80-0000R-26
R12 = RES_POT: part number: RES_POT_POT-BOURNS_3296Y,200K,80-0200K-F0A
R23 R201 R222 R235 R248 = RES: alternate symbols: 0402_NOSILK,RESC1005X50L,RES0402-NOT_FOR_TEST; part number: RES_0402RES-0402,100,80-0100R-23
R100 R118 = EK_RES_SMD: part number: EK_RES_SMD_0402_FF-RESC1005X50L,4.7K,80-004K7-23; signal model: DEFAULT_RESISTOR_4700OHM_2_1
R103 R123 = EK_RES_SMD: part number: EK_RES_SMD_0402_FF-RESC1005X50L,22,80-0022R-23; signal model: DEFAULT_RESISTOR_22.000000OHM_1_2
R107 R108 = EK_RES_SMD: part number: EK_RES_SMD_0402_FF-RESC1005X50L,2.2K,80-002K2-23; signal model: DEFAULT_RESISTOR_470.000000OHM_1_2
R109 R111 = EK_RES_SMD: part number: EK_RES_SMD_0402_FF-RESC1005X50L,100,80-0100R-23; signal model: DEFAULT_RESISTOR_100.000000OHM_2_1
R110 = RES: alternate symbols: (0402_NOSILK,RESC1005X50L); part number: RES_0402RES-0402,470,80-0470R-23
R115 = EK_RES_SMD: part number: EK_RES_SMD_0402_FF-RESC1005X50L,100K,80-0100K-23; signal model: DEFAULT_RESISTOR_100000OHM_1_2
R135 R136 R148 R152 R155 R162-R164 R166 = EK_RES_SMD: part number: EK_RES_SMD_0402_FF-RESC1005X50L,0,80-0000R-26; signal model: DEFAULT_RESISTOR_22.000000OHM_2_1
R137 R138 = EK_RES_SMD: part number: EK_RES_SMD_0402_FF-RESC1005X50L,49.9,80-049R9-23; signal model: DEFAULT_RESISTOR_49.900000OHM_1_2
R139 R141 R143 = EK_RES_SMD: part number: EK_RES_SMD_0402_FF-RESC1005X50L,0,80-0000R-26; signal model: DEFAULT_RESISTOR_0.001OHM_1_2
R150 = EK_RES_SMD: part number: EK_RES_SMD_0402_FF-RESC1005X50L,22,80-0022R-23; signal model: DEFAULT_RESISTOR_22.000000OHM_2_1
R151 = RES: alternate symbols: (0402_NOSILK,RESC1005X50L); part number: RES_0402RES-0402,150,80-0150R-23
R156 = RES: alternate symbols: (0402_NOSILK,RESC1005X50L); part number: RES_0402RES-0402,105K,80-0105K-18
R157 R159 R161 R214 R280 R283 = EK_RES_SMD: part number: EK_RES_SMD_0402_FF-RESC1005X50L,100K,80-0100K-23
R158 = RES: alternate symbols: (0402_NOSILK,RESC1005X50L); part number: RES_0402RES-0402,169K,80-0169K-23
R160 = RES: alternate symbols: (0402_NOSILK,RESC1005X50L); part number: RES_0402RES-0402,47.5K,80-047K5-23
R165 R213 R234 R247 R260 = EK_RES_SMD: alternate symbols: 0402,0402_NOSILK,; part number: EK_RES_SMD_0402_FF-RESC1005X50L,OPEN,N/A
R202 R223 R236 R249 = RES: alternate symbols: (0402_NOSILK,RESC1005X50L); part number: RES_0402RES-0402,680,80-0680R-23
R203 R224 R237 R250 = RES: alternate symbols: 0402_NOSILK,RESC1005X50L,RES0402-NOT_FOR_TEST; part number: RES_0402RES-0402,20K,80-0020K-23
R205 R206 R226 R228 R239 R240 R252 R253 = RES: alternate symbols: (0402_NOSILK,RESC1005X50L); part number: RES_0402RES-0402,4.99K,80-04K99-23
R207 R208 R229 R230 R242 R243 R254 R255 R263 R264 = EK_RES_SMD: part number: EK_RES_SMD_0402_FF-RESC1005X50L,1K,80-0001K-23
R210 R231 R244 R257 R301 = RES: alternate symbols: (0402_NOSILK,RESC1005X50L); part number: RES_0402RES-0402,1M,80-0001M-23
R211 R233 R245 R258 = RES: alternate symbols: (0603_NOSILK); part number: RES_0603RES-0603,1,80-0001R-24
R261 = RES: alternate symbols: (0603_NOSILK); part number: RES_0603RES-0603,0.1,80-000R1-AA14
R262 = RES: alternate symbols: (0603_NOSILK); part number: RES_0603RES-0603,10,80-0010R-24
R265-R268 = RES: alternate symbols: (0402_NOSILK,RESC1005X50L); part number: RES_0402RES-0402,64.9K,80-064K9-23
R269 = RES: alternate symbols: 0402_NOSILK,RESC1005X50L,RES0402-NOT_FOR_TEST; part number: RES_0402RES-0402,1K,80-0001K-23
R271-R274 = RES: alternate symbols: (0402_NOSILK,RESC1005X50L); part number: RES_0402RES-0402,10M,80-0010M-23
R294 R296 R298 R300 = RES: alternate symbols: 0402_NOSILK,RESC1005X50L; part number: RES_0402RES-0402,649K,80-0649K-AA18
RT1 = THERMISTOR_SMD: part number: THERMISTOR_SMD_0402-0402,10K,83-0010K-23A
SW0-SW8 = EVQ-Q2XXXX: part number: EVQ-Q2XXXX_SMT-SW_EVQ-Q2X03W,EVQ-Q2K03W,11-EVQQ2K03W-00
SW9 = CL-SB-12B-1X: part number: CL-SB-12B-1X_SMD-SW_CL-SB-12B-1X,CL-SB-12B-11,11-CLSB12B11-00
U1 = EK_MAX77278: alternate symbols: BGA35C40P7X5_314X214X69L; part number: EK_MAX77278_WLP35_1-BGA35C40P7X5_314X214X69M,MAX77278,N/A
U100 = MAXQ2000: part number: MAXQ2000_TQFN56-EP-QFN50P800X800X80-57M,MAXQ2000-RBX+,10-MAXQ2000RBX-T
U101 = FT232RQ: part number: FT232RQ_QFN32-EP-QFN50P500X500X100-33V2M,FT232RQ,10-FT232RQ-G
U102-U104 = MAX8512: part number: MAX8512_SC70-SOT65P210X110-5M,MAX8512EXK,10-MAX8512EXK-X
U107 = MAX3395E: part number: MAX3395E_TQFN-QFN80P400X400X80-13M,MAX3395EETC,10-MAX3395EETC-T
U108 = 24AA02: part number: 24AA02_SOT23-5-SOT95P280X145-5M,24AA02T-I/OT,10-24AA02TIOT-U
U200-U204 = MAX44251: part number: MAX44251_SPLIT_UMAX8-SOP65P490X110-8M,MAX44251AUA+,10-MAX44251AUA-U
U205 = MAX5815: part number: MAX5815_TSSOP14-SOP65P640X120-14M,MAX5815AAUD+,10-MAX5815AAUD-U
U206 = MAX14689: alternate symbols: BGA9C40P3X3_126X126X69L; part number: MAX14689_WLP9-BGA9C40P3X3_126X126X69M,MAX14689EWL+,10-MAX14689EWL-W
U207 = MAX4238: part number: MAX4238_SOT23-6-SOT95P280X145-6M,MAX4238AUT+,10-MAX4238AUT-U
U209 = MAX11614: part number: MAX11614_QSOP16-SOP63P600X175-16M,MAX11614EEE+,10-MAX11614EEE-U
U210 = MAX6037: part number: MAX6037_SOT23-5-SOT95P280X145-5M,MAX6037BAUK41+,10-MAX6037BAUK41-U
Y101 = XTAL: part number: XTAL_XTAL320X250X070M-XTAL320X250X070M,16MHZ,60-0016M-26A

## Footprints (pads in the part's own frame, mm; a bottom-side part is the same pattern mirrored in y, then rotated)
0402
  rect 0.762x0.584 smd: 1(-0.61,0) 2(0.61,0)
0402#2
  rect 0.4x0.5 smd: 1(-0.45,0) 2(0.45,0)
0603
  rect 0.69x0.83 smd: 1(-0.67,0) 2(0.67,0)
0603#2
  rect 0.965x0.762 smd: 1(-0.787,0) 2(0.787,0)
0805
  rect 1.35x1.55 smd: 1(-1,0) 2(1,0)
0805#2
  rect 0.94x1.37 smd: 1(-0.79,0) 2(0.79,0)
1206
  rect 0.85x1.67 smd: 1(-1.385,0) 2(1.385,0)
BGA9C40P3X3_126X126X69M
  round 0.254 smd: A1(-0.4,0.4) A2(0,0.4) A3(0.4,0.4) B1(-0.4,0) B2(0,0) B3(0.4,0) C1(-0.4,-0.4) C2(0,-0.4) C3(0.4,-0.4)
BGA35C40P7X5_314X214X69M
  round 0.254 smd: A1(-1.2,0.8) A2(-0.8,0.8) A3(-0.4,0.8) A4(0,0.8) A5(0.4,0.8) A6(0.8,0.8) A7(1.2,0.8) B1(-1.2,0.4) B2(-0.8,0.4) B3(-0.4,0.4) B4(0,0.4) B5(0.4,0.4) B6(0.8,0.4) B7(1.2,0.4) C1(-1.2,0) C2(-0.8,0) C3(-0.4,0) C4(0,0) C5(0.4,0) C6(0.8,0) C7(1.2,0) D1(-1.2,-0.4) D2(-0.8,-0.4) D3(-0.4,-0.4) D4(0,-0.4) D5(0.4,-0.4) D6(0.8,-0.4) D7(1.2,-0.4) E1(-1.2,-0.8) E2(-0.8,-0.8) E3(-0.4,-0.8) E4(0,-0.8) E5(0.4,-0.8) E6(0.8,-0.8) E7(1.2,-0.8)
BOURNS_3296Y
  rect 1.55x1.55 hole 0.95: 1(2.54,1.27)
  round 1.55 hole 0.95: 2(0,-1.27) 3(-2.54,1.27)
CAPC1005X50L
  rect 0.4x0.5 smd: 1(-0.45,0) 2(0.45,0)
CAPC1608X90L
  rect 0.69x0.83 smd: 1(-0.67,0) 2(0.67,0)
EVK_MAXIMPAD
  oval 5.08x1.905 hole 1: 1(0,0)
FCI_10103592-0001LF
  rect 0.4x1.65 smd: 1(1.3,2.925) 2(0.65,2.925) 3(0,2.925) 4(-0.65,2.925) 5(-1.3,2.925)
  custom 0.669x0.669 hole 0.7x1.3: 6(-4.1,0) 9(4.1,0)
  custom 0.35x0.35 hole 1.05x0.65: 7(-2.425,3.08) 8(2.425,3.08)
  rect 1.375x2.5 smd: 10(0.938,-0.2) 11(-0.938,-0.2)
IND_2016
  rect 0.9x1.6 smd: 1(-0.8,0) 2(0.8,0)
IND_2520
  rect 1.15x2.15 smd: 1(-1.015,0) 2(1.015,0)
JST_S2B-PH-K-X
  rect 1.55x1.55 hole 0.95: 1(0,0)
  round 1.55 hole 0.95: 2(-2,0)
LED_SFH47XX
  rect 2.8x0.55 smd: 1(0,1.125) 2(0,-1.125)
  rect 2.8x1 smd: 3(0,0)
LEDC1608X80M
  rect 1.1x1.05 smd: A(0.9,0) K(-0.9,0)
QFN50P500X500X100-33V2M
  oval 1x0.3 smd: 1(-2.5,1.75) 2(-2.5,1.25) 3(-2.5,0.75) 4(-2.5,0.25) 5(-2.5,-0.25) 6(-2.5,-0.75) 7(-2.5,-1.25) 8(-2.5,-1.75) 17(2.5,-1.75) 18(2.5,-1.25) 19(2.5,-0.75) 20(2.5,-0.25) 21(2.5,0.25) 22(2.5,0.75) 23(2.5,1.25) 24(2.5,1.75)
  oval 0.3x1 smd: 9(-1.75,-2.5) 10(-1.25,-2.5) 11(-0.75,-2.5) 12(-0.25,-2.5) 13(0.25,-2.5) 14(0.75,-2.5) 15(1.25,-2.5) 16(1.75,-2.5) 25(1.75,2.5) 26(1.25,2.5) 27(0.75,2.5) 28(0.25,2.5) 29(-0.25,2.5) 30(-0.75,2.5) 31(-1.25,2.5) 32(-1.75,2.5)
  rect 3.25x3.25 smd: 33(0,0)
QFN50P800X800X80-57M
  oval 0.9x0.3 smd: 1(-4,3.25) 2(-4,2.75) 3(-4,2.25) 4(-4,1.75) 5(-4,1.25) 6(-4,0.75) 7(-4,0.25) 8(-4,-0.25) 9(-4,-0.75) 10(-4,-1.25) 11(-4,-1.75) 12(-4,-2.25) 13(-4,-2.75) 14(-4,-3.25) 29(4,-3.25) 30(4,-2.75) 31(4,-2.25) 32(4,-1.75) 33(4,-1.25) 34(4,-0.75) 35(4,-0.25) 36(4,0.25) 37(4,0.75) 38(4,1.25) 39(4,1.75) 40(4,2.25) 41(4,2.75) 42(4,3.25)
  oval 0.3x0.9 smd: 15(-3.25,-4) 16(-2.75,-4) 17(-2.25,-4) 18(-1.75,-4) 19(-1.25,-4) 20(-0.75,-4) 21(-0.25,-4) 22(0.25,-4) 23(0.75,-4) 24(1.25,-4) 25(1.75,-4) 26(2.25,-4) 27(2.75,-4) 28(3.25,-4) 43(3.25,4) 44(2.75,4) 45(2.25,4) 46(1.75,4) 47(1.25,4) 48(0.75,4) 49(0.25,4) 50(-0.25,4) 51(-0.75,4) 52(-1.25,4) 53(-1.75,4) 54(-2.25,4) 55(-2.75,4) 56(-3.25,4)
  rect 6.7x6.7 smd: 57(0,0)
QFN80P400X400X80-13M
  oval 1.1x0.35 smd: 1(-1.9,0.8) 2(-1.9,0) 3(-1.9,-0.8) 7(1.9,-0.8) 8(1.9,0) 9(1.9,0.8)
  oval 0.35x1.1 smd: 4(-0.8,-1.9) 5(0,-1.9) 6(0.8,-1.9) 10(0.8,1.9) 11(0,1.9) 12(-0.8,1.9)
  rect 2.25x2.25 smd: 13(0,0)
RESC1005X50L
  rect 0.4x0.5 smd: 1(-0.45,0) 2(0.45,0)
RESC1608X90L
  rect 0.69x0.83 smd: 1(-0.67,0) 2(0.67,0)
SAMTEC_TSW-102-07-X-S
  rect 1.75x1.75 hole 1.15: 1(0,0)
  round 1.75 hole 1.15: 2(2.54,0)
SAMTEC_TSW-102-26-X-T
  rect 1.5x1.5 hole 0.9: 1(0,0)
  round 1.5 hole 0.9: 2(2.54,0) 3(0,-2.54) 4(2.54,-2.54) 5(0,-5.08) 6(2.54,-5.08)
SAMTEC_TSW-103-07-T-S
  rect 1.75x1.75 hole 1.15: 1(0,0)
  round 1.75 hole 1.15: 2(2.54,0) 3(5.08,0)
SOP63P600X175-16M
  rect 1.75x0.4 smd: 1(-2.8,2.223) 2(-2.8,1.588) 3(-2.8,0.953) 4(-2.8,0.318) 5(-2.8,-0.317) 6(-2.8,-0.952) 7(-2.8,-1.587) 8(-2.8,-2.222) 9(2.8,-2.223) 10(2.8,-1.588) 11(2.8,-0.953) 12(2.8,-0.318) 13(2.8,0.317) 14(2.8,0.952) 15(2.8,1.587) 16(2.8,2.222)
SOP65P490X110-8M
  rect 1.6x0.45 smd: 1(-2.35,0.975) 2(-2.35,0.325) 3(-2.35,-0.325) 4(-2.35,-0.975) 5(2.35,-0.975) 6(2.35,-0.325) 7(2.35,0.325) 8(2.35,0.975)
SOP65P640X120-14M
  rect 1.65x0.45 smd: 1(-3.05,1.95) 2(-3.05,1.3) 3(-3.05,0.65) 4(-3.05,0) 5(-3.05,-0.65) 6(-3.05,-1.3) 7(-3.05,-1.95) 8(3.05,-1.95) 9(3.05,-1.3) 10(3.05,-0.65) 11(3.05,0) 12(3.05,0.65) 13(3.05,1.3) 14(3.05,1.95)
SOT50P160X90-3M
  rect 1.05x0.4 smd: 1(-0.9,0.5) 2(-0.9,-0.5) 3(0.9,0)
SOT65P210X110-5M
  rect 1.1x0.45 smd: 1(-1.2,0.65) 2(-1.2,0) 3(-1.2,-0.65) 4(1.2,-0.65) 5(1.2,0.65)
SOT95P237X112-3M
  oval 1.6x0.65 smd: 1(-1.1,0.95) 2(-1.1,-0.95) 3(1.1,0)
SOT95P280X145-5M
  rect 1.25x0.65 smd: 1(-1.45,0.95) 2(-1.45,0) 3(-1.45,-0.95) 4(1.45,-0.95) 5(1.45,0.95)
SOT95P280X145-6M
  rect 1.25x0.65 smd: 1(-1.45,0.95) 2(-1.45,0) 3(-1.45,-0.95) 4(1.45,-0.95) 5(1.45,0) 6(1.45,0.95)
SULLINS_PXC06SAAN
  rect 1.75x1.75 hole 1.15: 1(0,0)
  round 1.75 hole 1.15: 2(2.54,0) 3(5.08,0) 4(7.62,0) 5(10.16,0) 6(12.7,0)
SULLINS_PXC08SAAN
  rect 1.75x1.75 hole 1.15: 1(0,0)
  round 1.75 hole 1.15: 2(2.54,0) 3(5.08,0) 4(7.62,0) 5(10.16,0) 6(12.7,0) 7(15.24,0) 8(17.78,0)
SW_CL-SB-12B-1X
  round 0.8 hole 0.9 unplated: (0,3.4) (0,-3.4)
  rect 1.4x1.2 smd: 1(-2.2,2.5) 2(2.2,0) 3(-2.2,-2.5)
SW_EVQ-Q2X03W
  rect 3.2x1 smd: 1(-3.4,-2.5) 2(3.4,-2.5) 3(-3.4,2.5) 4(3.4,2.5)
TP_180P120D460H
  round 1.6 hole 1: 1(0,0)
TP_C25H12
  round 0.635 hole 0.305: 1(0,0)
TP_C240H180
  round 2.4 hole 1.8: 1(0,0)
TP_C340H160
  round 3.4 hole 1.6: 1(0,0)
TRAN_IRF_PQFN8_SINGLE_B
  rect 0.77x0.39 smd: 1(-1.54,0.975) 2(-1.54,0.325) 3(-1.54,-0.325) 4(-1.54,-0.975) 6(1.54,-0.325) 7(1.54,0.325) 8(1.54,0.975)
  custom 0.635x0.635 smd: 5(1.54,-0.975)
unnamed#2
  round 5.08 hole 3.175: (0,0)
XTAL320X250X070M
  rect 1.4x1.2 smd: 1(-1.1,-0.8) 2(1.1,-0.8) 3(1.1,0.8) 4(-1.1,0.8)

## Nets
+1.8V: C111.2 J101.2 R160.1 U103.5
+2.5V: C113.2 C151.1 R156.1 U100.40 U104.5
+3.3V: C115.2 C150.1 C157.2 C158.2 C221.2 C222.2 D100.A D101.A D102.A D103.A J100.2 J101.4 R100.2 R118.2 R158.1 R163.2 R214.2 R283.1 R293.2 R294.1 R295.2 R296.1 R297.2 R298.1 R299.2 R300.1 U100.2 U100.22 U102.5 U107.11 U205.7 U205.13(VDDIO)
VBATT: C7.2 C15.1 J9.1 U1.E3 VBATT.1(TP1)
AMUX: AMUX.1(TP1) J2.2 R285.1 U1.C1
BST: C4.1 U1.C6
CHGIN: C2.2 CHGIN.1(TP1) J1.1 J4.1 U1.E1
CS: CS.1(TP1) J5.2 R9.2 U1.A5
CTSN: U100.39 U101.8
DCDN: U100.25 U101.7
DSRN: U100.24 U101.6
DTRN: U100.28 U101.31
GPIO0: GPIO0.1(TP1) R21.2 SW0.4 U1.B1
GPIO1: GPIO1.1(TP1) R19.2 SW1.4 U1.B2
GPIO2: GPIO2.1(TP1) R16.2 SW2.4 U1.B3
GPIO3: GPIO3.1(TP1) R6.2 SW3.4 U1.C2
GPIO4: GPIO4.1(TP1) R8.1 SW4.4 U1.D4
GPIO5: GPIO5.1(TP1) R18.1 SW5.4 U1.C3
GPIO6: GPIO6.1(TP1) R20.1 SW6.4 U1.C4
GPIO7: GPIO7.1(TP1) R22.1 SW7.4 U1.B4
GROUND: C1.1 C2.1 C3.1 C5.1 C6.1 C7.1 C8.1 C9.1 C10.2 C11.2 C12.1 C13.2 C14.1 C15.2 C16.1 C17.1 C18.1 C19.1 C20.1 C21.1 C22.1 C23.1 C24.1 C25.1 C26.1 C27.1 C28.1 C29.1 C30.1 C31.1 C32.1 C33.1 C34.1 C35.1 C36.1 C37.1 C38.1 C39.1 C108.1 C110.1 C111.1 C112.1 C113.1 C114.2 C115.1 C118.1 C120.1 C129.1 C134.1 C150.2 C151.2 C152.1 C153.1 C154.1 C155.2 C156.1 C157.1 C158.1 C159.2 C200.1 C202.2 C204.1 C205.1 C207.2 C208.1 C210.1 C212.2 C214.1 C215.1 C217.2 C218.1 C220.1 C221.1 C222.1 C223.1 C224.2 C226.2 C227.2 C228.1 C229.2 C234.1 C235.1 C236.1 C237.1 C238.1 C239.1 C240.1 C241.1 C242.1 C244.1 C248.1 C249.1 C250.1 C251.1 C252.1 GND1.1(TP1) GND2.1 GND3.1 GND4.1 GND5.1(TP1) GND6.1(TP1) GND7.1(TP1) GND8.1 J1.5 J2.8 J6.5 J7.3 J100.6 J208.1 Q1.2(S) Q100.2(S) Q101.2(S) Q204.2(S) Q206.2(S) R4.2 R7.2 R12.3 R13.2 R23.2 R110.2 R115.2 R122.2 R137.2 R138.2 R157.2 R159.2 R161.2 R166.2 R206.1 R208.2 R210.1 R211.2 R213.2 R226.1 R230.2 R231.1 R233.2 R234.2 R240.1 R243.2 R244.1 R245.2 R247.2 R252.1 R255.2 R257.1 R258.2 R260.2 R262.2 R268.2 R272.2 R274.2 R282.2 R287.2 R301.2 R307.1 R308.1 RT1.2 SW8.4 SW9.3 U1.A4 U1.E4 U1.E6 U100.1 U100.3 U100.4 U100.23 U100.35 U101.4 U101.17 U101.20 U101.24 U101.26 U101.33 U102.2 U103.2 U104.2 U107.5 U107.13 U108.2 U200.4 U201.4 U202.4 U203.4 U204.4 U205.4 U206.A3 U206.B2 U207.2 U209.15 U210.2 Y101.2 Y101.4
IBATT: C228.2 R269.2 U209.7
IBATT_SNS: BATTN.1(TP1) J9.2 J208.2 R261.1 U206.C1
IBATT_SNS_RNG: J100.5 Q204.1 R284.2 U206.A2
IN_SBB: C1.2 C16.2 IN_SBB.1(TP1) R5.2 U1.E5
INLDO: C13.1 C18.2 INLDO.1(TP1) R11.1 U1.B7
ISET_LDO: R250.1 U205.6
ISET_SBB0: R203.1 U205.2
ISET_SBB1: R224.1 U205.3
ISET_SBB2: R237.1 U205.5
LDO: C5.2 C17.2 C23.2 C25.2 C33.2 C36.2 C37.2 J207.2 LDO.1(TP1) U1.A7
LDO_DIV: U204.6 U204.7(OUTB) U209.11
LXA: L1.2 U1.D5
LXB: C4.2 L1.1 U1.D6
MAXQP03: PO3.1(TP1) U100.52
MAXQP05: PO5.1(TP1) U100.54
NEN: J2.3 J8.2 NEN.1(TP1) U1.C5
NIRQ: J2.4 NIRQ.1(TP1) R14.1 R150.2 U1.B5
NIRQ1: PO0.1(TP1) R152.1 U100.49
NRST: J2.5 NRST.1(TP1) R10.1 U1.B6
P01: PO1.1(TP1) R284.1 U100.50
P02: PO2.1(TP1) U100.51
P04: PO4.1(TP1) U100.53
P06: PO6.1(TP1) U100.55
P07: PO7.1(TP1) U100.56
REF_1: C236.2 C244.2 R265.1 R279.2 U209.1
RIN: U100.27 U101.3
RTSN: U100.26 U101.32
RXD: U100.43 U101.2
SBB0: C9.2 C19.2 C21.2 C27.2 C30.2 J201.2 R11.2 SBB0.1(TP1) U1.C7
SBB0_DIV: U204.1 U204.2 U209.8
SBB1: C8.2 C20.2 C22.2 C28.2 C31.2 J101.6 J203.2 SBB1.1(TP1) U1.D7
SBB2: C6.2 C24.2 C26.2 C29.2 C32.2 J205.2 SBB2.1(TP1) U1.E7
SCL: C134.2 J2.6 Q101.3 R107.2 R136.2 SCL.1(TP1) U1.A3
SCL1: J100.3 R118.1 R155.2 R162.1 R304.1 R305.1 U107.9
SDA: C129.2 J2.7 Q100.3 R108.2 R135.2 SDA.1(TP1) U1.A2
SDA1: J100.4 R100.1 R148.2 R164.2 R303.1 R306.1 U107.10
THM: J3.1 J3.3 J3.5 THM.1(TP1) U1.D2
THMB: R1.1 R12.1 R15.1 TBIAS.1(TP1) U1.D3
TXD: U100.44 U101.30
UNNAMED_1_10103592-0001LF_I172_SHIELD10: J1.6 J1.7 J1.8 J1.9(SHIELD9) J1.10 J1.11 R3.1 R4.1
UNNAMED_1_CAPNP_I179_2: C38.2 C39.2 DS2.2 DS2.3 LEDREM.1(TP1)
UNNAMED_1_CL-SB-12B-1X_I99_2: J8.3 SW9.2
UNNAMED_1_EKCAPNP_I55_1: C10.1 R3.2
UNNAMED_1_EKCAPNP_I69_2: C12.2 R17.1 U1.A1
UNNAMED_1_EKMAX77278_I115_CSEN: CS_EN.1(TP1) J7.2 U1.A6
UNNAMED_1_EVQ-Q2XXXX_I7_1: J8.1 Q1.3 R2.2 SW8.1
UNNAMED_1_EVQ-Q2XXXX_I149_1: R23.1 SW0.1 SW1.1 SW2.1 SW3.1 SW4.1 SW5.1 SW6.1 SW7.1
UNNAMED_1_HEADER2P_I176_1: DS2.1(K) J5.1
UNNAMED_1_HEADER2PX3R_I166_2: J3.2 R12.2
UNNAMED_1_HEADER2PX3R_I166_4: J3.4 R1.2 RT1.1
UNNAMED_1_HEADER2PX3R_I166_6: J3.6 R13.1 R15.2
UNNAMED_1_LED3P_I117_K: DS1.1(K) R9.1
UNNAMED_1_RESSMD_I170_1: EN_EXT.1(TP1) Q1.1 R7.1
UNNAMED_2_CAPNP_I23_1: C227.1 R264.2 R265.2 R268.1 U207.3
UNNAMED_2_CAPNP_I24_1: C225.1 R263.2 R266.1 R267.1 U207.4
UNNAMED_2_CAPNP_I24_2: C225.2 R266.2 R267.2 R269.1 U207.1
UNNAMED_2_CAPNP_I84_2: C238.2 R281.2 R282.1 U209.12
UNNAMED_2_CAPNP_I88_2: C249.2 R285.2 U209.5
UNNAMED_2_CAPNP_I90_2: C252.2 R301.1 R302.2 U209.6
UNNAMED_2_EKCAPNP_I56_2: C234.2 R277.2 R280.1 U210.4
UNNAMED_2_EKCAPNP_I61_2: C235.2 R279.1 U210.5(OUT)
UNNAMED_2_EKCAPNP_I74_2: C237.2 R286.2 U209.16(VDD)
UNNAMED_2_EKCAPNP_I107_2: C223.2 U205.1
UNNAMED_2_EKRESSMD_I63_2: R280.2 U210.3
UNNAMED_2_EKRESSMD_I79_2: R303.2 U209.14
UNNAMED_2_EKRESSMD_I80_2: R304.2 U209.13
UNNAMED_2_EKRESSMD_I93_1: AIN1.1(TP1) R302.1
UNNAMED_2_EKRESSMD_I109_2: R307.2 U205.9
UNNAMED_2_EKRESSMD_I110_2: R283.2 U205.12
UNNAMED_2_EKRESSMD_I111_2: R305.2 U205.10
UNNAMED_2_EKRESSMD_I112_2: R306.2 U205.11
UNNAMED_2_EKRESSMD_I113_2: R308.2 U205.8
UNNAMED_2_EKRESSMD_I114_1: R214.1 U205.14
UNNAMED_2_MAX14689_I1_COM1: R263.1 U206.B1
UNNAMED_2_MAX14689_I1_COM2: R264.1 U206.B3
UNNAMED_2_MAX14689_I1_NC1: Q204.3 R261.2 R262.1 U206.A1 U206.C3
UNNAMED_2_RESSMD_I81_1: AIN7.1(TP1) R281.1
UNNAMED_2_RESSMD_I95_2: Q205.1 Q206.3 R288.2
UNNAMED_4_24AA02_I200_SCL: R162.2 U108.1
UNNAMED_4_24AA02_I200_SDA: R164.1 U108.3
UNNAMED_4_24AA02_I200_VCC: C14.2 R163.1 R165.1 U108.4
UNNAMED_4_24AA02_I200_WP: R165.2 R166.1 U108.5(WP)
UNNAMED_4_10103592-0001LF_I212_1: C155.1 FB100.1 J6.1
UNNAMED_4_10103592-0001LF_I212_2: J6.2 R123.1
UNNAMED_4_10103592-0001LF_I212_3: J6.3 R103.1
UNNAMED_4_10103592-0001LF_I212_SHIELD10: J6.6 J6.7 J6.8 J6.9(SHIELD9) J6.10 J6.11 R122.1 R142.1
UNNAMED_4_CAPNP_I101_2: C153.2 U100.41 Y101.3(P2)
UNNAMED_4_CAPNP_I105_2: C152.2 U100.42 Y101.1
UNNAMED_4_EKCAPNP_I12_1: C156.2 C159.1 U101.1(VCCIO) U101.16
UNNAMED_4_EKCAPNP_I29_1: C114.1 R142.2
UNNAMED_4_EKRESSMD_I15_2: R123.2 U101.15
UNNAMED_4_EKRESSMD_I16_2: R103.2 U101.14
UNNAMED_4_EKRESSMD_I17_1: R111.1 U101.22
UNNAMED_4_EKRESSMD_I17_2: D100.K(B) R111.2
UNNAMED_4_EKRESSMD_I18_1: R109.1 U101.21
UNNAMED_4_EKRESSMD_I18_2: D101.K(B) R109.2
UNNAMED_4_EKRESSMD_I87_1: R150.1 U107.3
UNNAMED_4_EKRESSMD_I109_1: R155.1 U100.36
UNNAMED_4_EKRESSMD_I113_1: R148.1 U100.37
UNNAMED_4_EKRESSMD_I149_1: Q100.1 R138.1 R141.1
UNNAMED_4_EKRESSMD_I150_1: Q101.1 R137.1 R139.1
UNNAMED_4_EKRESSMD_I151_2: QSDA.1(TP1) R141.2
UNNAMED_4_EKRESSMD_I152_2: QSCL.1(TP1) R139.2
UNNAMED_4_EKRESSMD_I153_1: R135.1 U107.1
UNNAMED_4_EKRESSMD_I154_1: R136.1 U107.2
UNNAMED_4_EKRESSMD_I171_2: R143.2 U107.6
UNNAMED_4_EKRESSMD_I174_1: R156.2 R157.1 U104.4
UNNAMED_4_EKRESSMD_I177_1: R158.2 R159.1 U102.4
UNNAMED_4_EKRESSMD_I190_2: R151.2 R152.2 U107.8
UNNAMED_4_LED_I7_B: D102.K(B) R110.1
UNNAMED_4_LED_I189_B: D103.K(B) R151.1
UNNAMED_4_MAX3395E_I94_I: I/OVL4.1(TP1) U107.4
UNNAMED_4_MAX3395E_I94_I_1: I/OVCC4.1(TP1) U107.7
UNNAMED_4_MAX8512_I5_FB: R160.2 R161.1 U103.4
UNNAMED_6_CAPNP_I21_1: C203.1 R202.2 R205.1 U200.7(OUTB)
UNNAMED_6_CAPNP_I271_2: C208.2 R226.2 R229.1 R295.1 U201.5
UNNAMED_6_CAPNP_I277_1: C209.1 R223.2 R228.1 U201.7(OUTB)
UNNAMED_6_CAPNP_I277_2: C209.2 R228.2 R230.1 R296.2 U201.6
UNNAMED_6_CAPNP_I289_2: C248.2 R224.2 U201.3
UNNAMED_6_CAPNP_I307_2: C214.2 R240.2 R242.1 R297.1 U202.5
UNNAMED_6_CAPNP_I311_1: C213.1 R236.2 R239.1 U202.7(OUTB)
UNNAMED_6_CAPNP_I311_2: C213.2 R239.2 R243.1 R298.2 U202.6
UNNAMED_6_CAPNP_I323_2: C250.2 R237.2 U202.3
UNNAMED_6_CAPNP_I341_2: C218.2 R252.2 R254.1 R299.1 U203.5
UNNAMED_6_CAPNP_I345_1: C219.1 R249.2 R253.1 U203.7(OUTB)
UNNAMED_6_CAPNP_I345_2: C219.2 R253.2 R255.1 R300.2 U203.6
UNNAMED_6_CAPNP_I357_2: C251.2 R250.2 U203.3
UNNAMED_6_CAPNP_I359_2: C200.2 R203.2 U200.3
UNNAMED_6_EKCAPNP_I10_1: C201.1 R202.1 U200.2
UNNAMED_6_EKCAPNP_I10_2: C201.2 R201.1
UNNAMED_6_EKCAPNP_I237_2: C239.2 J201.1 Q200.5 Q200.6 Q200.7 Q200.8 R212.1
UNNAMED_6_EKCAPNP_I261_2: C240.2 J203.1 Q201.5 Q201.6 Q201.7 Q201.8 R227.1
UNNAMED_6_EKCAPNP_I287_1: C206.1 R223.1 U201.2
UNNAMED_6_EKCAPNP_I287_2: C206.2 R222.1
UNNAMED_6_EKCAPNP_I298_2: C241.2 J205.1 Q202.5 Q202.6 Q202.7 Q202.8 R246.1
UNNAMED_6_EKCAPNP_I321_1: C211.1 R236.1 U202.2
UNNAMED_6_EKCAPNP_I321_2: C211.2 R235.1
UNNAMED_6_EKCAPNP_I332_2: C242.2 J207.1 Q203.5 Q203.6 Q203.7 Q203.8 R259.1
UNNAMED_6_EKCAPNP_I355_1: C216.1 R249.1 U203.2
UNNAMED_6_EKCAPNP_I355_2: C216.2 R248.1
UNNAMED_6_EKRESSMD_I42_1: C204.2 R206.2 R207.1 R293.1 U200.5
UNNAMED_6_EKRESSMD_I42_2: Q200.1 Q200.2 Q200.3(S3) R207.2 R211.1 VIL_SBB0.1(TP1)
UNNAMED_6_EKRESSMD_I43_1: C203.2 R205.2 R208.1 R294.2 U200.6
UNNAMED_6_EKRESSMD_I99_1: R201.2 R204.1 U200.1
UNNAMED_6_EKRESSMD_I99_2: J200.1 R204.2
UNNAMED_6_EKRESSMD_I273_2: Q201.1 Q201.2 Q201.3(S3) R229.2 R233.1 VIL_SBB1.1(TP1)
UNNAMED_6_EKRESSMD_I278_1: R222.2 R225.1 U201.1
UNNAMED_6_EKRESSMD_I278_2: J202.1 R225.2
UNNAMED_6_EKRESSMD_I306_2: Q202.1 Q202.2 Q202.3(S3) R242.2 R245.1 VIL_SBB2.1(TP1)
UNNAMED_6_EKRESSMD_I313_1: R235.2 R238.1 U202.1
UNNAMED_6_EKRESSMD_I313_2: J204.1 R238.2
UNNAMED_6_EKRESSMD_I340_2: Q203.1 Q203.2 Q203.3(S3) R254.2 R258.1 VIL_LDO.1(TP1)
UNNAMED_6_EKRESSMD_I347_1: R248.2 R251.1 U203.1
UNNAMED_6_EKRESSMD_I347_2: J206.1 R251.2
UNNAMED_6_HEADER2P_I444_2: J202.2 Q201.4 R231.2
UNNAMED_6_HEADER2P_I446_2: J204.2 Q202.4 R244.2
UNNAMED_6_HEADER2P_I448_2: J206.2 Q203.4 R257.2
UNNAMED_6_MAX44251_I450_INA: R271.2 R272.1 U204.3
UNNAMED_6_MAX44251_I451_INB: R273.2 R274.1 U204.5
UNNAMED_6_RESSMD_I28_2: J200.2 Q200.4 R210.2
UNNAMED_7_EVKITINDUCT_I24_1: L2.1 L3.1 L4.1 L5.1
UNNAMED_7_EVKITINDUCT_I24_2: L2.2 L3.2 L4.2 L5.2
VADC: Q205.2(S) R277.1 R286.1 R288.1
VIO: C120.2 J2.1 J7.1 J101.1 J101.3 J101.5 R10.2 R14.2 R17.2 R107.1 R108.1 R143.1 U107.12(VL)
VL: C3.2 U1.D1(VL) VL.1(TP1)
VLDO: C220.2 R259.2 R260.1 R273.1
VSBB0: C205.2 R212.2 R213.1 R271.1
VSBB1: C210.2 R227.2 R234.1 U209.9
VSBB2: C215.2 R246.2 R247.1 U209.10
VSYS: C11.1 C34.2 C35.2 DS1.2 DS1.3 R2.1 R5.1 R6.1 R8.2 R16.1 R18.2 R19.1 R20.2 R21.1 R22.2 SW9.1 U1.E2 VSYS.1(TP1)
VUSB: C108.2 C110.2 C112.2 C118.2 C154.2 C202.1 C207.1 C212.1 C217.1 C224.1 C226.1 C229.1 FB100.2 J4.2 J100.1 Q205.3 Q206.1 R115.1 R287.1 U101.19 U102.1 U102.3(SHDN*) U103.1 U103.3(SHDN*) U104.1 U104.3(SHDN*) U200.8 U201.8 U202.8 U203.8 U204.8 U206.C2(VCC) U207.5 U207.6(VCC)

Pads without a net: J1 2 3 4; J6 4; SW0 2 3; SW1 2 3; SW2 2 3; SW3 2 3; SW4 2 3; SW5 2 3; SW6 2 3; SW7 2 3; SW8 2 3; U100 5 6 7 8 9 10 11 12 13 14 15 16 17 18 19 20 21 29 30 31 32 33 34 38 45 46 47 48 57; U101 5 9 10 11 12 13 18 23 25 27 28 29; U209 2 3 4; U210 1

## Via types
v1: diameter 0.457, hole 0.203, TOP to BOTTOM, 413 vias
v2: diameter 0.203, hole 0.102, TOP to INTERNAL2, 94 vias
v3: diameter 0.406, hole 0.203, INTERNAL2 to INTERNAL3, 20 vias
v4: diameter 0.457, hole 0.203, INTERNAL3 to BOTTOM, 82 vias

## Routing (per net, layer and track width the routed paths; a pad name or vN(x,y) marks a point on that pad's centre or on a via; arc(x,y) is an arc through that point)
+1.8V: length 37.3
  TOP w0.254: 40.83,90.92 40.56,91.19 38.07,91.19 37.53,90.64 C111.2 37.56,90.35 U103.5
  TOP w0.381: v1(41.33,90.92) 40.84,90.92 40.83,90.92 40.83,90.01 R160.1
  BOTTOM w0.381: J101.2 67.82,89.03 61.44,89.03 59.54,90.92 v1(41.33,90.92)
+2.5V: length 26.3
  TOP w0.254: v1(24.23,88.9) 24.82,88.9 C151.1 24.26,88.89 24.02,89.12 U100.40 ; v1(41.68,88.7) 41.91,88.7 42.21,89 U104.5 44.14,89.29 43.69,89.74 43.69,90.37 C113.2 43.68,91.19 R156.1
  BOTTOM w0.254: v1(24.23,88.9) 24.84,88.9 25.04,88.7 v1(41.68,88.7)
+3.3V: length 255.8
  TOP w0.254: v1(11.13,81.58) v1(16.76,81.58) 16.92,81.43 C150.1 17.18,81.64 17.26,81.72 17.26,81.74 17.33,81.81 17.35,81.81 18.03,82.49 U100.22 ; 31.62,90.17 C158.2 ; D103.A v1(36.66,78.78) ; v1(11.13,89.59) 11.95,89.59 11.98,89.62 U100.2 ; 27.56,86.85 R118.2 ; v1(56.11,81.43) 56.09,81.45 R163.2 ; D100.A D101.A
  TOP w0.381: 34.64,90.88 R158.1 ; 34.64,90.88 34.51,91.01 32.04,91.01 31.66,90.63 C158.2 ; 34.64,90.88 34.71,90.96 v1(36.75,90.96) ; v1(28.56,89.36) 29.03,89.36 29.14,89.47 D102.A 30.23,90.13 31,90.13 31.12,90.25 31.55,90.25 31.62,90.17 U102.5 ; v1(36.66,71.25) 35.67,70.26 D100.A ; U107.11 28.56,82.21 28.79,82.44 28.79,83.11 C115.2 28.58,83.3 C157.2 28.12,83.06 v1(28.12,82.72) ; R100.2 27.56,86.85 ; v1(30.09,84.92) v1(28.12,84.92) 27.58,85.46 R118.2
  TOP w0.508: 32.99,91.01 32.94,91.06 J100.2
  INTERNAL3 w0.254: v4(69.93,83.99) v4(69.93,82.03) ; v1(11.13,81.58) v1(11.13,89.59) ; v1(56.08,83.94) 56.08,83.33 56.11,83.3 v1(56.11,81.43)
  INTERNAL3 w0.381: v4(65.08,83.99) v4(65.08,74.85) 65.08,74.18 65.41,73.86 v1(65.41,68.12) ; v4(76.83,31.39) v4(76.83,29.9) ; v4(76.77,38.03) 76.77,38.71 76.65,38.83 v4(76.65,39.54) ; v1(28.56,89.36) 28.56,88.1 30.09,86.57 v1(30.09,84.92) ; v4(76.18,49.24) v4(76.18,47.92) ; v4(70.46,32.61) v4(70.46,41.17) 70.46,42.11 70.71,42.37 v4(70.71,51.59) 70.71,67.34 70.76,67.39 v4(70.76,68.12) ; v1(28.12,82.72) v1(28.12,84.92) ; v4(75.76,66.79) v4(75.76,64.18)
  INTERNAL3 w0.508: J101.4 65.08,88.83 v4(65.08,83.99) ; v1(36.66,71.25) v1(36.66,78.78) 36.66,79.52 36.75,79.61 v1(36.75,90.96)
  BOTTOM w0.254: v4(69.93,83.99) 70.03,84.08 C221.2 ; v4(69.93,83.99) 69.31,83.99 ; v4(69.93,83.99) 70.36,83.56 R214.2 ; 69.31,83.99 69.31,83.98 69.31,83.59 R283.1 ; 69.31,83.99 v4(65.08,83.99) ; v1(56.08,83.94) 56.11,83.96 57.56,83.96 57.58,83.99 ; U205.7 v4(65.08,74.85) 65.04,74.81 C222.2 ; U205.13 69.93,80.97 v4(69.93,82.03)
  BOTTOM w0.381: R298.1 76.29,29.9 v4(76.83,29.9) ; v4(70.71,51.59) 74.04,51.59 75.75,49.88 R293.2 v4(76.18,49.24) ; v1(65.41,68.12) v4(70.76,68.12) 74.75,68.12 75.26,67.61 R299.2 v4(75.76,66.79) ; J101.4 66.17,89.92 61.8,89.92 60.03,91.68 37.48,91.68 v1(36.75,90.96) ; v4(76.65,39.54) R295.2 76.14,39.85 74.81,41.17 v4(70.46,41.17) ; v4(76.83,31.39) R297.2 76.3,32.06 75.74,32.61 v4(70.46,32.61) ; v4(75.76,64.18) 75.27,64.18 R300.1 ; R294.1 75.74,47.92 v4(76.18,47.92) ; v1(28.12,82.72) 20.8,82.72 20.78,82.71 17.98,82.71 17.33,82.06 17.24,82.06 v1(16.76,81.58) ; v4(76.77,38.03) R296.1
  BOTTOM w0.508: 57.58,83.99 v4(65.08,83.99)
